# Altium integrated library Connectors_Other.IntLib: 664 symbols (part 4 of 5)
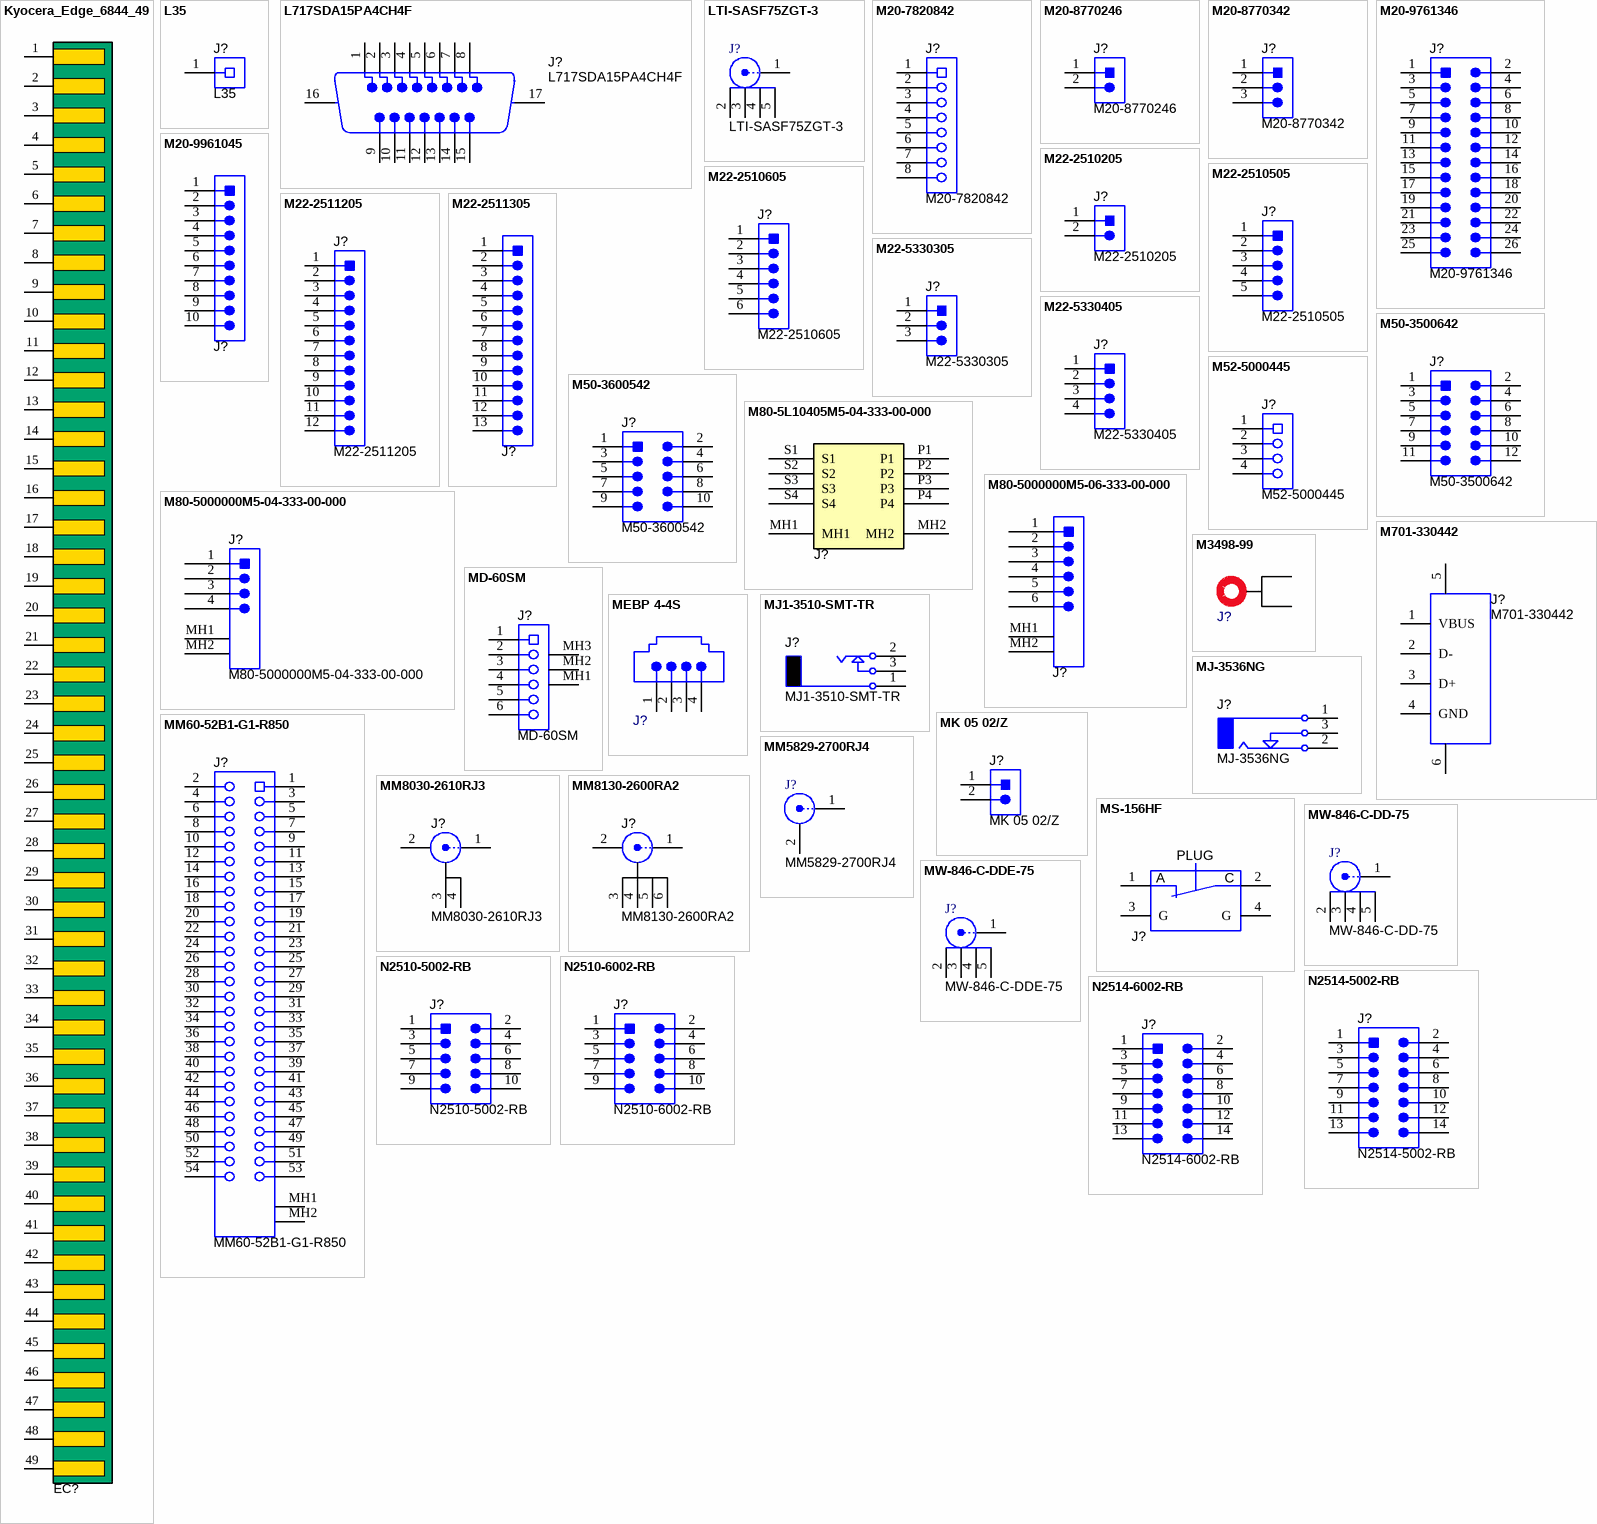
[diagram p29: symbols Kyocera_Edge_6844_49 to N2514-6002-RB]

## M80-5000000M5-04-333-00-000
designator J?
Connector, 4mm, 4x1, Gold, Black, R/A, TH; Manufacturer: Harwin; SymbolCreator: Altium; Pitch_mm: 4; Gender: Male; Shrouded: Y; Row_Count: 1; Current_A: 20
footprint Harwin_M80-5000000M5-04-333-00-000
pins: 1, 2, 3, 4, MH1, MH2

## M80-5000000M5-06-333-00-000
designator J?  (value not drawn)
Connector, 4mm, 6x1, Gold, Black, R/A, TH; Manufacturer: Harwin; SymbolCreator: Altium; Pitch_mm: 4; Gender: Male; Shrouded: Y; Row_Count: 1; Current_A: 20
footprint Harwin_M80-5000000M5-06-333-00-000
pins: 1, 2, 3, 4, 5, 6, MH1, MH2

## M701-330442
designator J?
USB Type B, Gold, White, TH; Manufacturer: Harwin; SymbolCreator: a0412235; Pitch_mm: 2.5; Gender: Female; Shrouded: Y; Row_Count: 2; RowSpacing_mm: 3.2; Current_A: 1.5; Voltage_V: 30
footprint Harwin_M701-330442
pins: 1 VBUS "+5V", 2 D- "Data -", 3 D+ "Data +", 4 GND "Ground", 5 Shield, 6 Shield

## M3498-99
designator J?  (value not drawn)
PC Tail Test Jack, TH; Manufacturer: Harwin; SymbolCreator: Altiumn; Pitch_mm: 10.16; Gender: Female; Row_Count: 1; ContactFinish: Gold; Current_A: 5; Voltage_V: 1500; Cert_UL: Y
footprint Harwin_M3498-99
pins: 1, 2

## MD-60SM
designator J?
Connector, Mini DIN, 3Pos, R/A, TH; Manufacturer: CUI Inc.; SymbolCreator: x0208325; Green_Lifecycle: Not Set; Green_REACh: Incomplete
footprint CUI_MD-60SM
pins: 1, 2, 3, 4, 5, 6, MH1, MH2, MH3

## MEBP 4-4S
designator J?  (value not drawn)
Modular Jack, RJ10, 4P4C, R/A, Gold, TH; Manufacturer: Reichelt; SymbolCreator: Altium; CompType: Connector; Pitch_mm: 1.27; Gender: Female; Row_Count: 2; RowSpacing_mm: 2.54; Cert_UL: Y
footprint Reichelt_MEBP_4-4S
pins: 1, 2, 3, 4

## MJ1-3510-SMT-TR
designator J?
Audio Jack, 3.5mm, Mono, R/A, Black, SMT; Manufacturer: CUI Inc.; SymbolCreator: Altium; CompType: Audio Connector; Gender: Female; ContactFinish: Gold; Current_A: 0.3; Voltage_V: 16
footprint CUI_MJ1-3510
pins: 1 SLEEVE, 2 TIP, 3 TIP SWITCH

## MJ-3536NG
designator J?
Audio Jack, 3.5mm, R/A, Black, TH; Manufacturer: CUI Inc.; SymbolCreator: Altium; CompType: Audio Connector
footprint CUI_MJ-3536NG
pins: 1 SLEEVE, 2 TIP, 3 TIP SWITCH

## MK 05 02/Z
designator J?
Header, 2.54 mm, 2x1, TH; Manufacturer: Fischer Elektronik; SymbolCreator: a0412235
footprint Fischer_MK_05_02
pins: 1, 2
1 alternate drawing of the same symbol

## MM60-52B1-G1-R850
designator J?
Receptacle, 2mm, 27x2, SMD; Manufacturer: JAE Electronics; SymbolCreator: x0208325
footprint JAE_MM60-52B1-G1-R850
pins: 1, 2, 3, 4, 5, 6, 7, 8, 9, 10, 11, 12, 13, 14, 15, 16, 17, 18, 19, 20, 21, 22, 23, 24, 25, 26, 27, 28, 29, 30, 31, 32, 33, 34, 35, 36, 37, 38, 39, 40, 41, 42, 43, 44, 45, 46, 47, 48, 49, 50, 51, 52, 53, 54, MH1, MH2

## MM5829-2700RJ4
designator J?
Connector, RF, 50 Ohm, SMT; Manufacturer: MuRata; SymbolCreator: a0799628; Gender: Male; Shrouded: Y; ContactFinish: Gold
footprint MuRata_MM5829-2700
pins: 1, 2

## MM8030-2610RJ3
designator J?
Coaxial Connectors with Switch, 50 Ohm, SMD; Manufacturer: MuRata; SymbolCreator: Altium; Green_Lifecycle: Not Set; Green_REACh: Incomplete
footprint MuRata_MM8030-2610
pins: 1 IN, 2 OUT, 3 GND (power), 4 GND

## MM8130-2600RA2
designator J?
Coaxial Connectors with Switch, 50 Ohm, SMD; Manufacturer: MuRata; SymbolCreator: a0411947; Gender: Male; Row_Count: 1; ContactFinish: Tin
footprint MuRata_MM8130-2600
pins: 1 IN, 2 OUT, 3 GND, 4 GND (power), 5 GND, 6 GND (power)

## MS-156HF
designator J?  (value not drawn)
CONN COAX JACK STR 50 OHM, SMD; Manufacturer: Hirose Electric Co. Ltd.; SymbolCreator: Altium; CompType: Receptacle; Gender: Female; ContactFinish: Gold; Current_A: 0.1; Voltage_V: 100; Cert_UL: Y
footprint Hirose_MS-156HF
pins: 1 A "NC", 2 C "COM", 3 G, 4 G

## MW-846-C-DD-75
designator J?
F Female Edge Mount, SMT; Manufacturer: Millimeter Wave Technologies; SymbolCreator: X0208326
footprint MWT_MW-846-C-DD-75
pins: 1, 2, 3, 4, 5

## MW-846-C-DDE-75
designator J?
F Female Edge Mount, SMT; Manufacturer: Millimeter Wave Technologies; SymbolCreator: X0208326; Green_Lifecycle: Not Set; Green_REACh: Incomplete
footprint MWT_MW-846-C-DDE-75
pins: 1, 2, 3, 4, 5

## N2510-5002-RB
designator J?
Header (Shrouded), 2.54mm, 5x2, R/A, Gold, Black, TH; Manufacturer: 3M; SymbolCreator: a0412235; Pitch_mm: 2.54; Gender: Male; Shrouded: Y; Row_Count: 2; Current_A: 1.75; Voltage_V: 500
footprint 3M_N2510-50xx
pins: 1, 2, 3, 4, 5, 6, 7, 8, 9, 10

## N2510-6002-RB
designator J?
Header (shrouded), 100mil, 5x2, High-Temperature, Gold, TH; Manufacturer: 3M; SymbolCreator: a0412235; Green_Lifecycle: Active; Green_REACh: Passed
footprint CONN_2510-6002
pins: 1, 2, 3, 4, 5, 6, 7, 8, 9, 10

## N2514-5002-RB
designator J?
Header (shrouded), 100mil, 7x2,  Gold, R/A, TH; Manufacturer: 3M; SymbolCreator: a0412235
footprint CONN_3M_N2514-5002-RB
pins: 1, 2, 3, 4, 5, 6, 7, 8, 9, 10, 11, 12, 13, 14

## N2514-6002-RB
designator J?
Header (shrouded), 100mil, 7x2, Gold, TH; Manufacturer: 3M; SymbolCreator: a0412235; Green_Lifecycle: Active; Green_REACh: Passed
footprint 3M_x2514-60xx
pins: 1, 2, 3, 4, 5, 6, 7, 8, 9, 10, 11, 12, 13, 14

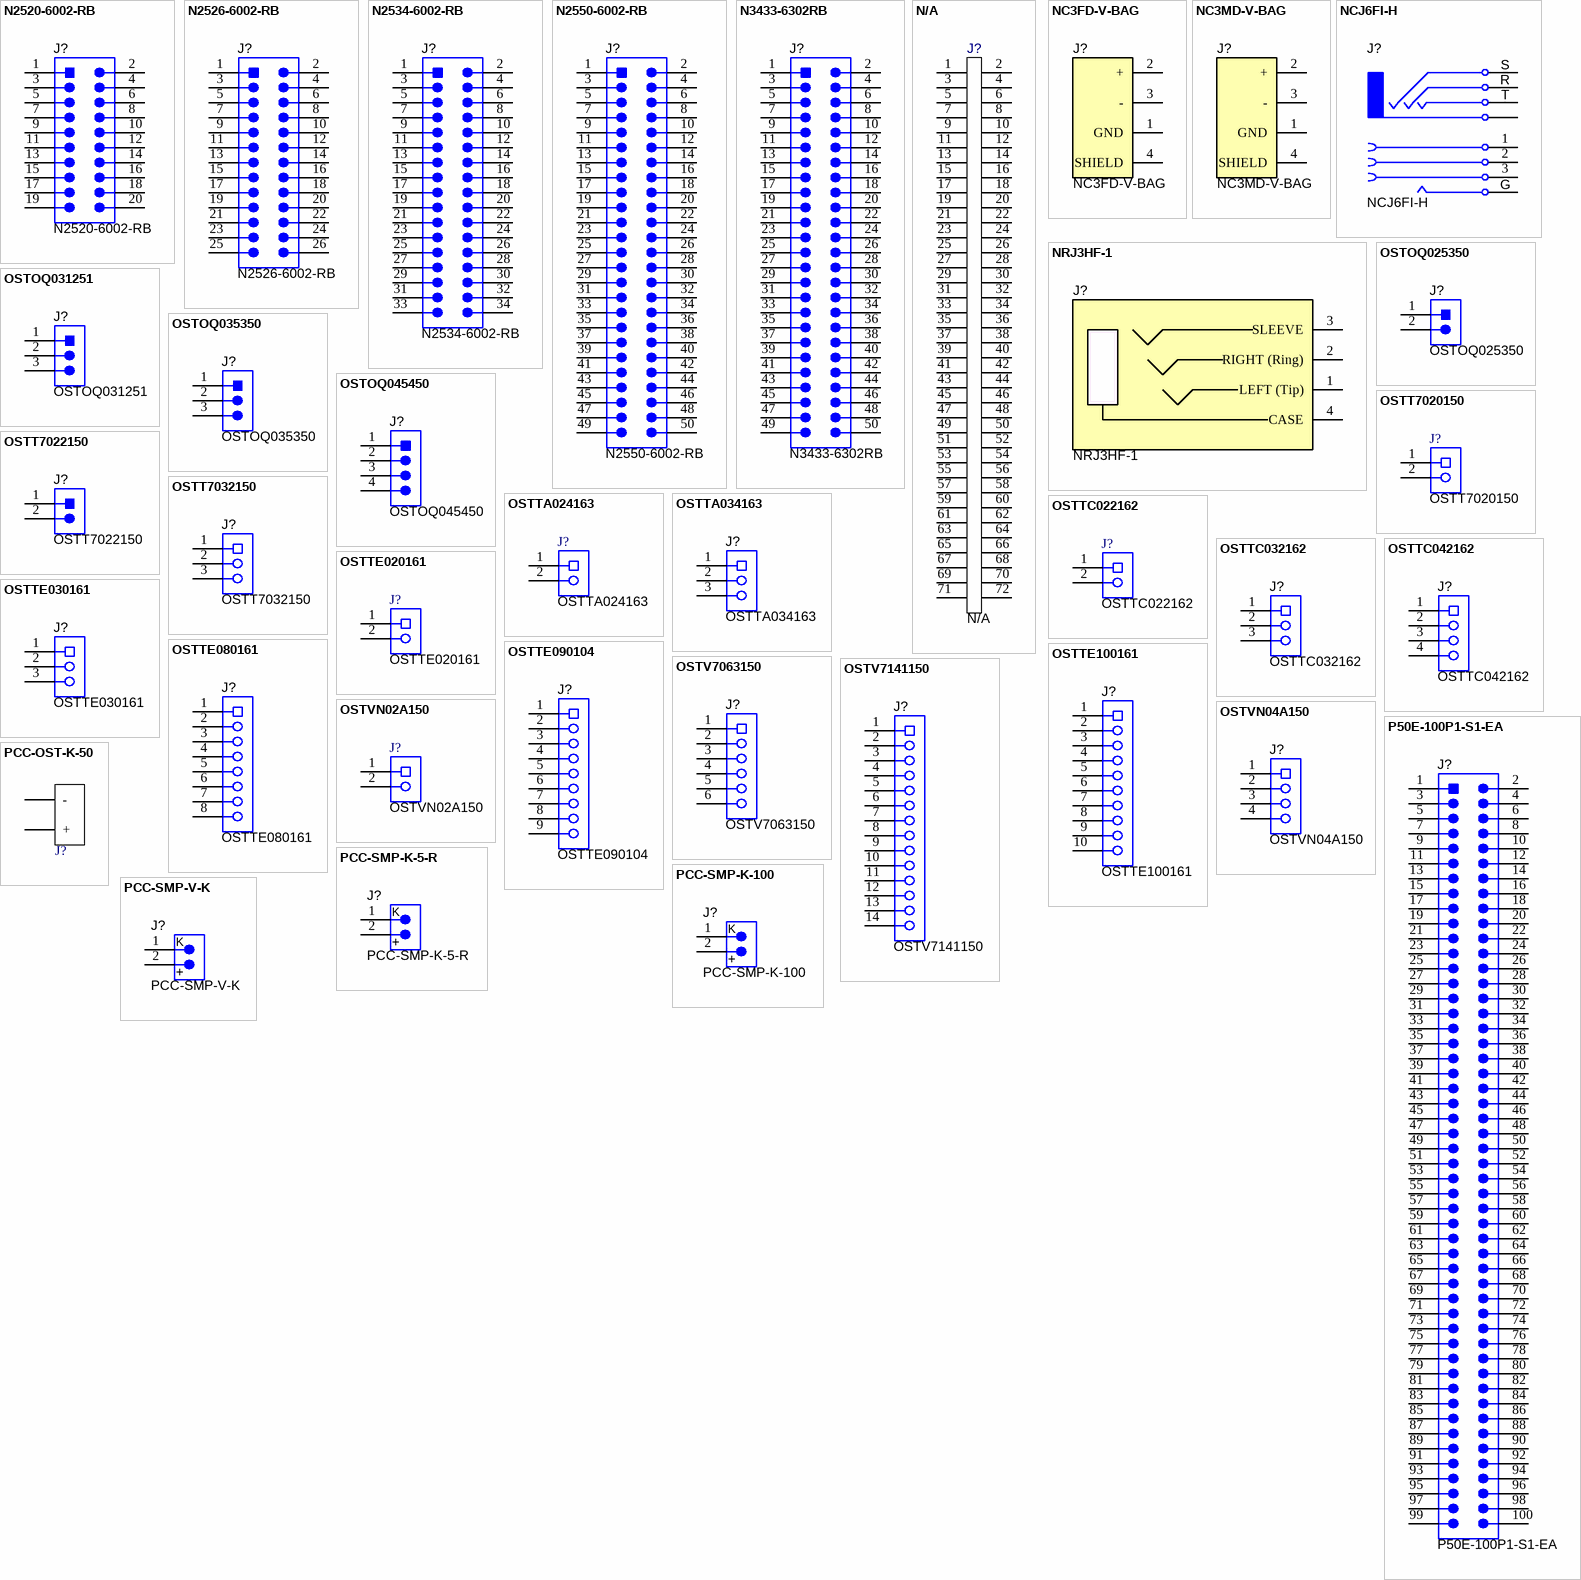
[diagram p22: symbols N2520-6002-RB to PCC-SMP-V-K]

## N2520-6002-RB
designator J?
Header (Shrouded), 2.54mm, 10x2, Gold, Black, TH; Manufacturer: 3M; SymbolCreator: a0412235; Pitch_mm: 2.54; Gender: Male; Shrouded: Y; Row_Count: 2; Green_Lifecycle: Active; Green_REACh: Passed
footprint 3M_N2520-6002
pins: 1, 2, 3, 4, 5, 6, 7, 8, 9, 10, 11, 12, 13, 14, 15, 16, 17, 18, 19, 20

## N2526-6002-RB
designator J?
Header (shrouded), 100mil, 13x2, Gold, TH; Manufacturer: 3M; SymbolCreator: a0412235; Green_Lifecycle: Active; Green_REACh: Passed
footprint CONN_2526-6002
pins: 1, 2, 3, 4, 5, 6, 7, 8, 9, 10, 11, 12, 13, 14, 15, 16, 17, 18, 19, 20, 21, 22, 23, 24, 25, 26

## N2534-6002-RB
designator J?
Header (shrouded), 2.54 mm, 17x2, Gold, TH; Manufacturer: 3M; SymbolCreator: a0411947; Green_Lifecycle: Active; Green_REACh: Passed
footprint 3M_N2534-6002
pins: 1, 2, 3, 4, 5, 6, 7, 8, 9, 10, 11, 12, 13, 14, 15, 16, 17, 18, 19, 20, 21, 22, 23, 24, 25, 26, 27, 28, 29, 30, 31, 32, 33, 34

## N2550-6002-RB
designator J?
Header(Shrouded), 2.54mm, 25x2, Gold, TH; Manufacturer: 3M; SymbolCreator: a0799628; Pitch_mm: 2.54; Gender: Male; Shrouded: Y; Row_Count: 2; Green_Lifecycle: Active; Green_REACh: Passed
footprint 3M_N2550-6002-RB
pins: 1, 2, 3, 4, 5, 6, 7, 8, 9, 10, 11, 12, 13, 14, 15, 16, 17, 18, 19, 20, 21, 22, 23, 24, 25, 26, 27, 28, 29, 30, 31, 32, 33, 34, 35, 36, 37, 38, 39, 40, 41, 42, 43, 44, 45, 46, 47, 48, 49, 50

## N3433-6302RB
designator J?
Header (shrouded), 100mil, 25x2, Gold, TH; Manufacturer: 3M; SymbolCreator: a0799628
footprint 3M_N3433-6302RB
pins: 1, 2, 3, 4, 5, 6, 7, 8, 9, 10, 11, 12, 13, 14, 15, 16, 17, 18, 19, 20, 21, 22, 23, 24, 25, 26, 27, 28, 29, 30, 31, 32, 33, 34, 35, 36, 37, 38, 39, 40, 41, 42, 43, 44, 45, 46, 47, 48, 49, 50

## N/A
designator J?  (no BOM)
Edge Connector; SymbolCreator: a0412235; CompType: Card Edge Footprint
footprint Edge_Connector_36x2
pins: 1, 2, 3, 4, 5, 6, 7, 8, 9, 10, 11, 12, 13, 14, 15, 16, 17, 18, 19, 20, 21, 22, 23, 24, 25, 26, 27, 28, 29, 30, 31, 32, 33, 34, 35, 36, 37, 38, 39, 40, 41, 42, 43, 44, 45, 46, 47, 48, 49, 50, 51, 52, 53, 54, 55, 56, 57, 58, 59, 60, 61, 62, 63, 64, 65, 66, 67, 68, 69, 70, 71, 72

## NC3FD-V-BAG
designator J?
Receptacle, 3 Poles, Vertical, TH; Manufacturer: Neutrik; SymbolCreator: Altium
footprint Neutrik_NC3FD-V
pins: 1 GND, 2 +, 3 -, 4 SHIELD

## NC3MD-V-BAG
designator J?
Connector, 3 pole male receptacle, TH; Manufacturer: Neutrik; SymbolCreator: Altium; Shrouded: Y
footprint Neutrik_NC3MD-V-BAG
pins: 1 GND, 2 +, 3 -, 4 SHIELD

## NCJ6FI-H
designator J?
XLR Receptacle and 1/4" Phone Jack, 8-Pin, TH; Manufacturer: Neutrik; SymbolCreater: Altium; CompType: Audio Connector; Green_Lifecycle: Not Set; Green_REACh: Incomplete
footprint Neutrik_NCJ6FI-H
pins: 1 "Tip/Left Channel/(+)", 2, 3, 4 G (power) "Sleeve (Ground)", 5 S, 6 R, 7 T, 8

## NRJ3HF-1
designator J?
Phone Jack, 1/4", TH; Manufacturer: Neutrik; SymbolCreator: Altium; CompType: Audio Connector; Green_Lifecycle: Not Set; Green_REACh: Incomplete
footprint Neutrik_NRJ3HF-1
pins: 1 LEFT (Tip), 2 RIGHT (Ring), 3 SLEEVE, 4 CASE

## OSTOQ025350
designator J?
Header(shrouded), 5.08mm, 2x1, Tin, TH; Manufacturer: On-Shore Technology; SymbolCreator: a0412235; Pitch_mm: 5.08; Gender: Male; Shrouded: Y; Row_Count: 1; Current_A: 20; Voltage_V: 300
footprint On-Shore_OSTOQ025350
pins: 1, 2
1 alternate drawing of the same symbol

## OSTOQ031251
designator J?
Terminal Block, 3.5mm, 3x1, TH; Manufacturer: On-Shore Technology; SymbolCreator: a0799628; Note: Mating Part number: OSTTJ0311530
footprint On-Shore_OSTOQ031251
pins: 1, 2, 3
3 alternate drawings of the same symbol

## OSTOQ035350
designator J?
Header(shrouded), 5.08mm, 3x1, Tin, TH; Manufacturer: On-Shore Technology; SymbolCreator: a0799628; Pitch_mm: 5.08; Gender: Male; Shrouded: Y; Row_Count: 1; Current_A: 20; Voltage_V: 300
footprint On-Shore_OSTOQ035350
pins: 1, 2, 3
3 alternate drawings of the same symbol

## OSTOQ045450
designator J?
Header(shrouded), 5.08mm, 4x1, Tin, Green, TH; Manufacturer: On-Shore Technology; SymbolCreator: a0412235; Pitch_mm: 5.08; Gender: Male; Shrouded: Y; Row_Count: 1; Current_A: 20; Voltage_V: 300
footprint On-Shore_OSTOQ045450
pins: 1, 2, 3, 4

## OSTT7020150
designator J?
Terminal Block, 6.35mm, 2x1, TH; Manufacturer: On-Shore Technology; SymbolCreator: a0412235; Pitch_mm: 6.35; Gender: Female; Row_Count: 1; Current_A: 30; Voltage_V: 300; Cert_UL: Y
footprint On-Shore_OSTT7020150
pins: 1, 2

## OSTT7022150
designator J?
Terminal Block, 30A, 9.52mm (.375) Pitch, 2-Pos, TH; Manufacturer: On-Shore Technology; SymbolCreator: a0412235; Green_Lifecycle: Not Set; Green_REACh: Incomplete
footprint TERM_BLK_OSTT7022150
pins: 1, 2
1 alternate drawing of the same symbol

## OSTT7032150
designator J?
Terminal Block, 3x1, 9.52mm, TH; Manufacturer: On-Shore Technology; SymbolCreator: a0412235; Pitch_mm: 9.52; Gender: Female; Row_Count: 1; ContactFinish: Brass; Green_Lifecycle: Not Set; Green_REACh: Incomplete
footprint On-Shore_OSTT7032150
pins: 1, 2, 3

## OSTTA024163
designator J?
Terminal Block, 2x1, 5.08mm, TH; Manufacturer: On-Shore Technology; SymbolCreator: a0412235; Green_Lifecycle: Not Set; Green_REACh: Incomplete
footprint On-Shore_OSTTA024163
pins: 1, 2

## OSTTA034163
designator J?
Terminal Block, 3x1, 5.08 mm, TH; Manufacturer: On-Shore Technology; SymbolCreator: a0412235; Green_Lifecycle: Not Set; Green_REACh: Incomplete
footprint On-Shore_OSTTA034163
pins: 1, 2, 3

## OSTTC022162
designator J?
Terminal Block, 2-pole, 200mil, TH; Manufacturer: On-Shore Technology; SymbolCreator: a0412235; Green_Lifecycle: Not Set; Green_REACh: Incomplete
footprint On-Shore_OSTTC022162
pins: 1, 2

## OSTTC032162
designator J?
Terminal Block, 3x1, 5.08 mm, Tin, TH; Manufacturer: On-Shore Technology; SymbolCreator: a0412235; Pitch_mm: 5.08; Gender: Female; Row_Count: 1; Current_A: 15; Voltage_V: 300; Cert_UL: Y
footprint On-Shore_OSTTC032162
pins: 1, 2, 3

## OSTTC042162
designator J?
Terminal Block, 5.08 mm, 4x1, Tin, Blue, TH; Manufacturer: On-Shore Technology; SymbolCreator: a0411947
footprint On-Shore_OSTTC042162
pins: 1, 2, 3, 4

## OSTTE020161
designator J?
Terminal Block, 2x1, 3.5mm, TH; Manufacturer: On-Shore Technology; SymbolCreator: a0412235; Green_Lifecycle: Not Set; Green_REACh: Incomplete
footprint On-Shore_OSTTE020161
pins: 1, 2

## OSTTE030161
designator J?
Terminal Block, 3.5mm, 3x1, Tin, R/A, TH; Manufacturer: On-Shore Technology; SymbolCreator: a0412235; Pitch_mm: 3.5; Gender: Female; Row_Count: 1; Current_A: 10; Voltage_V: 125; Cert_CSA: Y; Green_Lifecycle: Not Set; Green_REACh: Incomplete
footprint On-Shore_OSTTE030161
pins: 1, 2, 3

## OSTTE080161
designator J?
Terminal Block, 8x1, 3.5mm, TH; Manufacturer: On-Shore Technology; SymbolCreator: a0411947; Green_Lifecycle: Not Set; Green_REACh: Incomplete
footprint On-Shore_OSTTE080161
pins: 1, 2, 3, 4, 5, 6, 7, 8

## OSTTE090104
designator J?
Terminal Block, 3.5mm, 9x1, TH; Manufacturer: On-Shore Technology; SymbolCreator: x0208325; Pitch_mm: 3.5; Gender: Female; Row_Count: 1; ContactFinish: Tin; Current_A: 10; Voltage_V: 125; Cert_UL: Y
footprint On-Shore_OSTTE090104
pins: 1, 2, 3, 4, 5, 6, 7, 8, 9

## OSTTE100161
designator J?
Terminal Block, 3.5mm, 10x1, Tin, Blue, TH; Manufacturer: On-Shore Technology; SymbolCreator: a0411947; Pitch_mm: 3.5; Gender: Female; Row_Count: 1; Current_A: 10; Voltage_V: 125; Cert_CSA: Y; Green_Lifecycle: Not Set; Green_REACh: Incomplete
footprint On-Shore_OSTTE100161
pins: 1, 2, 3, 4, 5, 6, 7, 8, 9, 10

## OSTV7063150
designator J?
Terminal Block, 3.81mm, 6x1, Tin, TH; Manufacturer: On-Shore Technology; SymbolCreator: a0411947; Pitch_mm: 3.81; Gender: Female; Row_Count: 1; Current_A: 8; Voltage_V: 300; Cert_UL: Y
footprint On-Shore_OSTV7063150
pins: 1, 2, 3, 4, 5, 6

## OSTV7141150
designator J?
Terminal Block, 3.5mm, 14x1, Tin, TH; Manufacturer: On-Shore Technology; SymbolCreator: a0411947; Pitch_mm: 3.5; Gender: Female; Row_Count: 1; Current_A: 8; Voltage_V: 300; Cert_UL: Y
footprint On-Shore_OSTV7141150
pins: 1, 2, 3, 4, 5, 6, 7, 8, 9, 10, 11, 12, 13, 14

## OSTVN02A150
designator J?
Terminal Block, 2.54mm, 2x1, Brass, TH; Manufacturer: On-Shore Technology; SymbolCreator: a0412235; Green_Lifecycle: Not Set; Green_REACh: Incomplete
footprint On-Shore_OSTVN02A150
pins: 1, 2

## OSTVN04A150
designator J?
Terminal Block, 2.54mm, 4x1, Brass, TH; Manufacturer: On-Shore Technology; SymbolCreator: a0411947
footprint On-Shore_OSTVN04A150
pins: 1, 2, 3, 4

## P50E-100P1-S1-EA
designator J?
Header, 1.27mm, 50x2, Gold, TH; Manufacturer: 3M; SymbolCreator: a0799628; Pitch_mm: 1.25; Gender: Male; Row_Count: 2
footprint 3M_P50E-100P1-S1-xx
pins: 1, 2, 3, 4, 5, 6, 7, 8, 9, 10, 11, 12, 13, 14, 15, 16, 17, 18, 19, 20, 21, 22, 23, 24, 25, 26, 27, 28, 29, 30, 31, 32, 33, 34, 35, 36, 37, 38, 39, 40, 41, 42, 43, 44, 45, 46, 47, 48, 49, 50, 51, 52, 53, 54, 55, 56, 57, 58, 59, 60, 61, 62, 63, 64, 65, 66, 67, 68, 69, 70, 71, 72, 73, 74, 75, 76, 77, 78, 79, 80, 81, 82, 83, 84, 85, 86, 87, 88, 89, 90, 91, 92, 93, 94, 95, 96, 97, 98, 99, 100

## PCC-OST-K-50
designator J?  (value not drawn)
Connector, TH, Thermocouple type K; Manufacturer: Omega; Value: Type K; U/M: EA
footprint PCC-OST
pins: 1 -, 2 +

## PCC-SMP-K-5-R
designator J?
Circuit Board Thermocouple Connector, Miniature Size, Type K, Horizontal installation, TH; Manufacturer: Omega; SymbolCreator: a0799628
footprint Omega_PCC-SMP-K
pins: 1, 2
1 alternate drawing of the same symbol

## PCC-SMP-K-100
designator J?
Thermocouple Connectors, Type PCC, TH; Manufacturer: Omega; SymbolCreator: a0799628
footprint Omega_PCC-SMP-K
pins: 1, 2
1 alternate drawing of the same symbol

## PCC-SMP-V-K
designator J?
Thermocouple Connectors, Type PCC, TH; Manufacturer: Omega; SymbolCreator: a0799628
footprint Omega_PCC-SMP-V-K
pins: 1, 2
1 alternate drawing of the same symbol

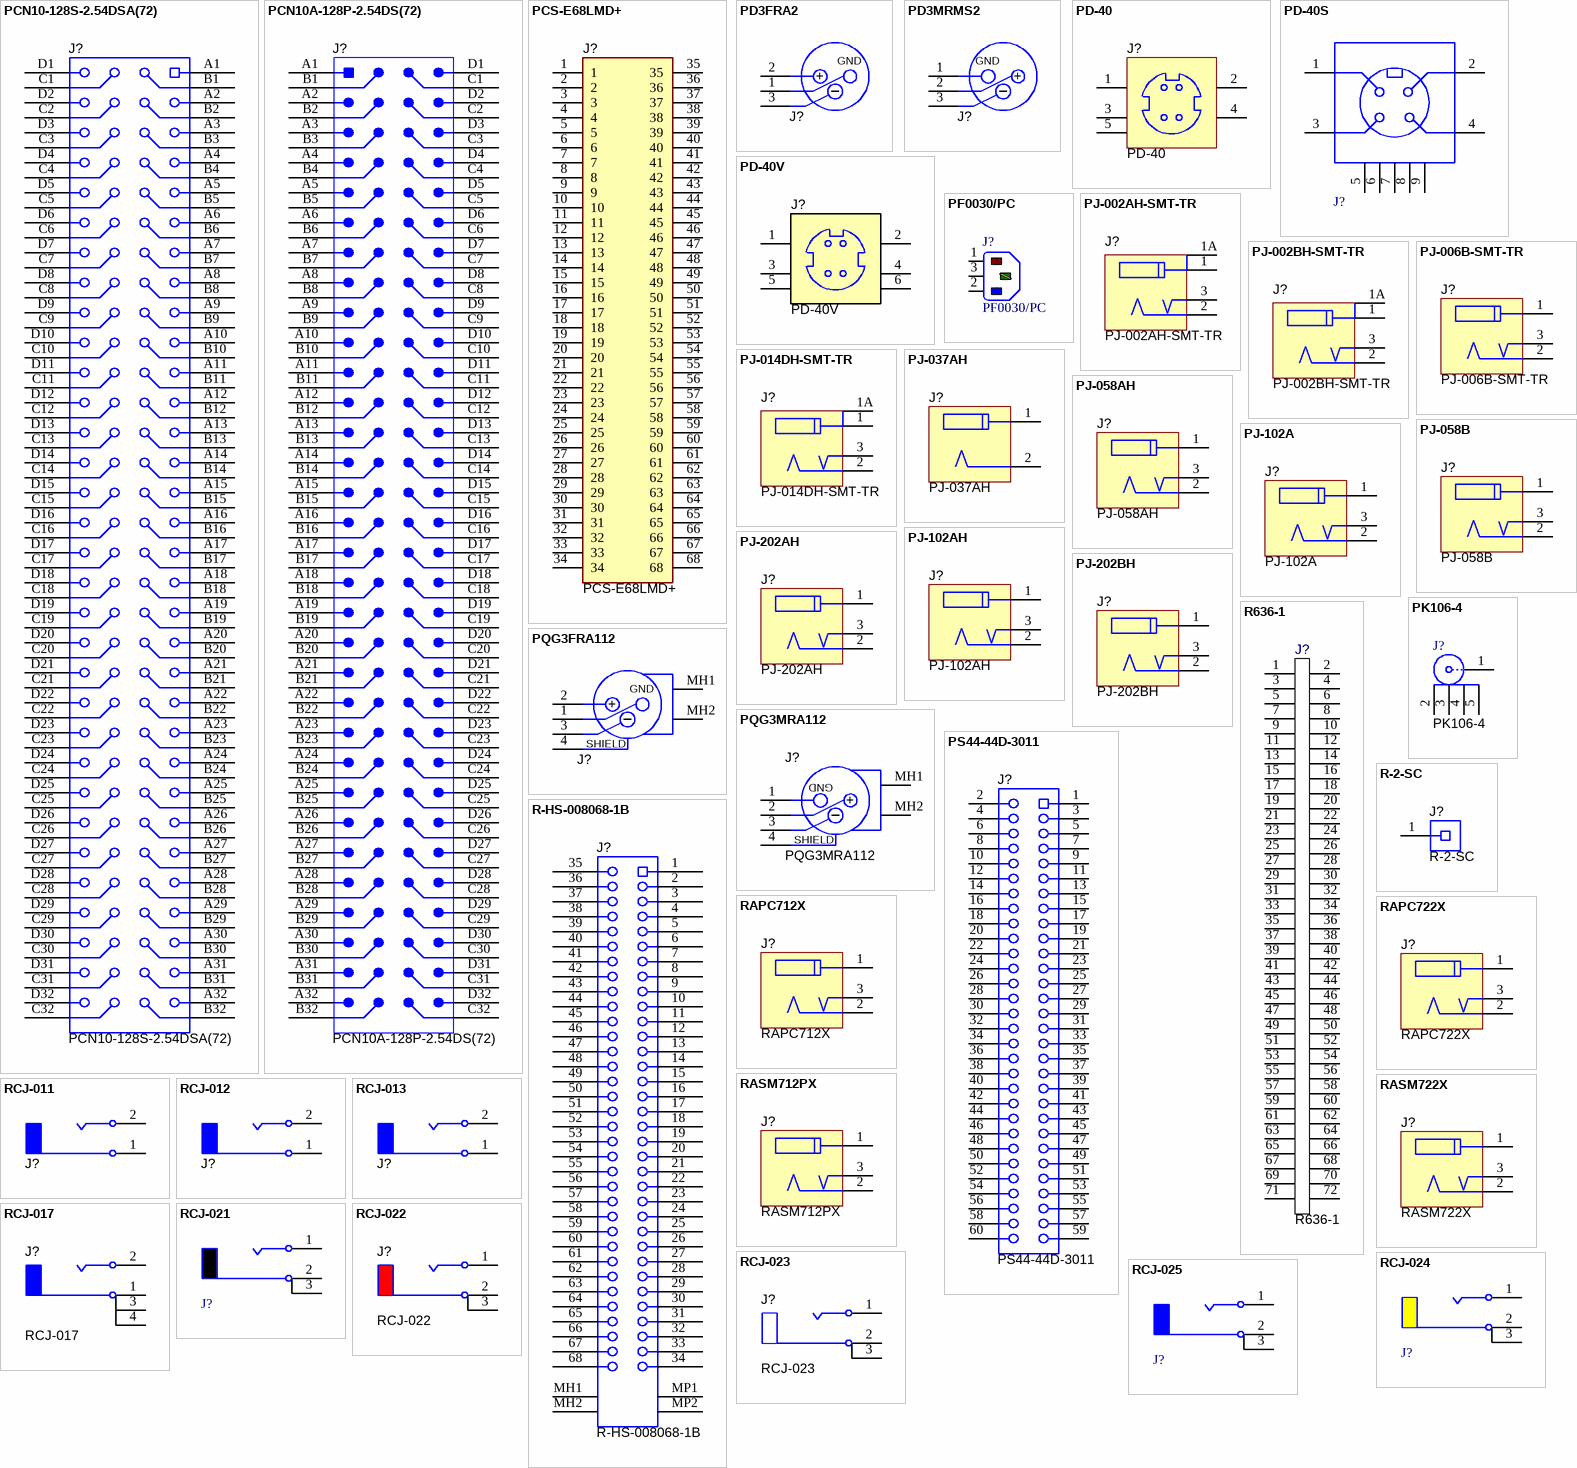
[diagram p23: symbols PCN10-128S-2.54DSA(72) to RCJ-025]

## PCN10-128S-2.54DSA(72)
designator J?
Receptacle, 2.54mm, 32x4, Gold, TH; Manufacturer: Hirose Electric Co. Ltd.; SymbolCreator: Altium; Pitch_mm: 2.54; Gender: Female; Row_Count: 4
footprint Hirose_PCN10-128S-2_54DSA_72
pins: A1, A2, A3, A4, A5, A6, A7, A8, A9, A10, A11, A12, A13, A14, A15, A16, A17, A18, A19, A20, A21, A22, A23, A24, A25, A26, A27, A28, A29, A30, A31, A32, B1, B2, B3, B4, B5, B6, B7, B8, B9, B10, B11, B12, B13, B14, B15, B16, B17, B18, B19, B20, B21, B22, B23, B24, B25, B26, B27, B28, B29, B30, B31, B32, C1, C2, C3, C4, C5, C6, C7, C8, C9, C10, C11, C12, C13, C14, C15, C16, C17, C18, C19, C20, C21, C22, C23, C24, C25, C26, C27, C28, C29, C30, C31, C32, D1, D2, D3, D4, D5, D6, D7, D8, D9, D10, D11, D12, D13, D14, D15, D16, D17, D18, D19, D20, D21, D22, D23, D24, D25, D26, D27, D28, D29, D30, D31, D32

## PCN10A-128P-2.54DS(72)
designator J?
Header, 2.54mm, 32x4, Gold, R/A, TH; Manufacturer: Hirose Electric Co. Ltd.; SymbolCreator: Altium; Pitch_mm: 2.54; Gender: Male; Row_Count: 4
footprint Hirose_PCN10A-128P-2_54DS_72
pins: A1, A2, A3, A4, A5, A6, A7, A8, A9, A10, A11, A12, A13, A14, A15, A16, A17, A18, A19, A20, A21, A22, A23, A24, A25, A26, A27, A28, A29, A30, A31, A32, B1, B2, B3, B4, B5, B6, B7, B8, B9, B10, B11, B12, B13, B14, B15, B16, B17, B18, B19, B20, B21, B22, B23, B24, B25, B26, B27, B28, B29, B30, B31, B32, C1, C2, C3, C4, C5, C6, C7, C8, C9, C10, C11, C12, C13, C14, C15, C16, C17, C18, C19, C20, C21, C22, C23, C24, C25, C26, C27, C28, C29, C30, C31, C32, D1, D2, D3, D4, D5, D6, D7, D8, D9, D10, D11, D12, D13, D14, D15, D16, D17, D18, D19, D20, D21, D22, D23, D24, D25, D26, D27, D28, D29, D30, D31, D32

## PCS-E68LMD+
designator J?
Connector, SCSI, M, 68-Pos, 1.27mm Pitch, R/A, TH; Manufacturer: Honda Tsushin Kogyo; SymbolCreator: a0799721
footprint CONN_PCS-E68LMD+
pins: 1, 2, 3, 4, 5, 6, 7, 8, 9, 10, 11, 12, 13, 14, 15, 16, 17, 18, 19, 20, 21, 22, 23, 24, 25, 26, 27, 28, 29, 30, 31, 32, 33, 34, 35, 36, 37, 38, 39, 40, 41, 42, 43, 44, 45, 46, 47, 48, 49, 50, 51, 52, 53, 54, 55, 56, 57, 58, 59, 60, 61, 62, 63, 64, 65, 66, 67, 68

## PD3FRA2
designator J?  (value not drawn)
Receptacle, 3 Contacts, Tin, R/A, TH; Manufacturer: Switchcraft; SymbolCreator: Altium; Pitch_mm: 4; Gender: Female
footprint Switchcraft_PD3FRA2
pins: 1 GND, 2 +, 3 -

## PD3MRMS2
designator J?  (value not drawn)
Connector, Male Pin, 3 Contacts, Silver, R/A, TH; Manufacturer: Switchcraft; SymbolCreator: Altium; Pitch_mm: 4; Shrouded: Y
footprint Switchcraft_PD3MRMS2
pins: 1 GND, 2 +, 3 -

## PD-40
designator J?
Power Jack, Tin, R/A, TH; Manufacturer: CUI Inc.; SymbolCreator: Altium
footprint CUI_PD-40
pins: 1, 2, 3, 4, 5

## PD-40S
designator J?  (value not drawn)
Power DIN Jack, 4 Pos, R/A, Tin, TH; Manufacturer: CUI Inc.; SymbolCreator: Altium; Gender: Female; Current_A: 7.5; Voltage_V: 20
footprint CUI_PD-40S
pins: 1, 2, 3  , 4  , 5  , 6  , 7   (power), 8   (power), 9

## PD-40V
designator J?
Power Jack, Silver, TH; Manufacturer: CUI Inc.; SymbolCreator: Altium; Gender: Female; Shrouded: N
footprint CUI_PD-40V
pins: 1, 2, 3, 4, 5, 6

## PF0030/PC
designator J?
IEC Connector, PC Flange Mount Fused Inlet, 10A, 250V, TH; Manufacturer: Bulgin; SymbolCreator: Altium; CompType: Socket
footprint Bulgin_PF0030_PC
pins: 1 L (power) "Live (Active)", 2 N (power) "Neutral", 3 E (power) "Earth (Ground)"

## PJ-002AH-SMT-TR
designator J?
Power Jack, SMT; Manufacturer: CUI Inc.; SymbolCreator: a0411947; Green_Lifecycle: Not Set; Green_REACh: Incomplete
footprint CUI_PJ-002AH-SMT
pins: 1, 1A, 2, 3

## PJ-002BH-SMT-TR
designator J?
Power Jack, 2.5x5.5mm, R/A, SMT; Manufacturer: CUI Inc.; SymbolCreator: a0411947; Pitch_mm: 6.1; Gender: Female; Row_Count: 2; RowSpacing_mm: 11.4; ContactFinish: Silver; Current_A: 5; Voltage_V: 24; Cert_UL: Y
footprint CUI_PJ-002BH-SMT-TR
pins: 1, 1A, 2, 3

## PJ-006B-SMT-TR
designator J?
DC Power Jack, SMT; Manufacturer: CUI Inc.; SymbolCreator: a0799628; Gender: Male; Current_A: 4; Voltage_V: 18; Cert_UL: Y
footprint CUI_PJ-006B-SMT-TR
pins: 1, 2, 3

## PJ-014DH-SMT-TR
designator J?
Power Jack, Nickel, R/A, SMD; Manufacturer: CUI Inc.; SymbolCreator: a0411947
footprint CUI_PJ-014DH-SMT-TR
pins: 1, 1A, 2, 3

## PJ-037AH
designator J?
Power Jack, 2mm, R/A, TH; Manufacturer: CUI Inc.; SymbolCreator: Altium; Pitch_mm: 6; Gender: Male; Shrouded: N; Row_Count: 1
footprint CUI_PJ-037AH
pins: 1, 2

## PJ-058AH
designator J?
Connector, DC Jack 2.5 mm Center Pin, TH; Manufacturer: CUI Inc.; SymbolCreator: a0799628; CompType: Power Jack; Green_Lifecycle: Not Set; Green_REACh: Incomplete
footprint CUI_PJ-058AH
pins: 1, 2, 3

## PJ-058B
designator J?
Connector, DC Jack 2.5 mm Center Pin, TH; Manufacturer: CUI Inc.; SymbolCreator: a0799628; CompType: Power Jack; Gender: Female; ContactFinish: Nickel; Current_A: 2.5; Voltage_V: 24; Cert_UL: Y
footprint CUI_PJ-058B
pins: 1, 2, 3

## PJ-102A
designator J?
Connector, DC Jack 2.1X5.5 mm, TH; Manufacturer: CUI Inc.; SymbolCreator: a0799628; Green_Lifecycle: Not Set; Green_REACh: Incomplete
footprint CONN_PJ-102A
footprint CUI_PJ-102A_NoSlots
pins: 1, 2, 3

## PJ-102AH
designator J?
DC POWER JACK, R/A, TH; Manufacturer: CUI Inc.; SymbolCreator: a0799628; Gender: Male; Current_A: 5; Voltage_V: 24; Cert_UL: Y; Green_Lifecycle: Not Set; Green_REACh: Incomplete
footprint CUI_PJ-102AH
pins: 1, 2, 3

## PJ-202AH
designator J?
Connector, DC Jack 2.1X5.5 mm, TH; Manufacturer: CUI Inc.; SymbolCreator: a0799628; CompType: Power Jack; Green_Lifecycle: Not Set; Green_REACh: Incomplete
footprint CONN_CUI-PJ-202AH
footprint CONN_CUI-PJ-202AH_NoSlots
pins: 1, 2, 3

## PJ-202BH
designator J?
Connector, DC Jack 2.5 mm Center Pin, TH; Manufacturer: CUI Inc.; SymbolCreator: a0799628; CompType: Power Jack
footprint CUI_PJ-202BH
footprint CUI_PJ-202BH_NoSlots
pins: 1, 2, 3

## PK106-4
designator J?
Probe Tip to PCB Adapter, TH; Manufacturer: Teledyne LeCroy
footprint Lecroy_PK106-4
pins: 1, 2, 3, 4, 5

## PQG3FRA112
designator J?  (value not drawn)
Receptacle, 160mil, 3 Position, R/A, TH; Manufacturer: Switchcraft; SymbolCreator: Altium; Pitch_mm: 4.1; Gender: Female; Shrouded: Y; Row_Count: 1; Green_Lifecycle: Not Set; Green_REACh: Incomplete
footprint Switchcraft_PQG3FRA112
pins: 1 GND, 2 +, 3 -, 4 SHIELD, MH1, MH2

## PQG3MRA112
designator J?
Receptacle, Male, 3 Position, R/A, TH; Manufacturer: Switchcraft; SymbolCreator: Altium; Green_Lifecycle: Not Set; Green_REACh: Incomplete
footprint Switchcraft_PQG3MRA112
pins: 1 GND, 2 +, 3 -, 4 SHIELD, MH1, MH2

## PS44-44D-3011
designator J?
Edge Card Connector, 2.54, 44x2, TH; Manufacturer: Yamaichi Electronics; SymbolCreator: Altium; CompType: Card Edge Socket; Pitch_mm: 2.54; Gender: Female; Row_Count: 2; Current_A: 3; Voltage_V: 100
footprint Yamaichi_PS44-44D-3011
pins: 1, 2, 3, 4, 5, 6, 7, 8, 9, 10, 11, 12, 13, 14, 15, 16, 17, 18, 19, 20, 21, 22, 23, 24, 25, 26, 27, 28, 29, 30, 31, 32, 33, 34, 35, 36, 37, 38, 39, 40, 41, 42, 43, 44, 45, 46, 47, 48, 49, 50, 51, 52, 53, 54, 55, 56, 57, 58, 59, 60
1 alternate drawing of the same symbol

## R636-1
designator J?
Edge Connector; Manufacturer: Vector Electronics; SymbolCreator: a0412235
footprint R636-1
pins: 1, 2, 3, 4, 5, 6, 7, 8, 9, 10, 11, 12, 13, 14, 15, 16, 17, 18, 19, 20, 21, 22, 23, 24, 25, 26, 27, 28, 29, 30, 31, 32, 33, 34, 35, 36, 37, 38, 39, 40, 41, 42, 43, 44, 45, 46, 47, 48, 49, 50, 51, 52, 53, 54, 55, 56, 57, 58, 59, 60, 61, 62, 63, 64, 65, 66, 67, 68, 69, 70, 71, 72

## R-2-SC
designator J?
Pin Receptacle, Gold, TH; Manufacturer: Interconnect Devices; SymbolCreator: a0799628; Gender: Female; Current_A: 3
footprint IDI_R-2-SC
pins: 1

## R-HS-008068-1B
designator J?
Receptacle, 0.8 mm, 34x2, Gold, TH; Manufacturer: All Best Electronics; SymbolCreator: Altium
footprint ALLBEST_R-HS-008068-1B
pins: 1, 2, 3, 4, 5, 6, 7, 8, 9, 10, 11, 12, 13, 14, 15, 16, 17, 18, 19, 20, 21, 22, 23, 24, 25, 26, 27, 28, 29, 30, 31, 32, 33, 34, 35, 36, 37, 38, 39, 40, 41, 42, 43, 44, 45, 46, 47, 48, 49, 50, 51, 52, 53, 54, 55, 56, 57, 58, 59, 60, 61, 62, 63, 64, 65, 66, 67, 68, MH1, MH2, MP1, MP2

## RAPC712X
designator J?
Power Jack, mini, 2.5mm OD, R/A, TH; Manufacturer: Switchcraft; SymbolCreator: a0799628; Green_Lifecycle: Not Set; Green_REACh: Incomplete
footprint CONN_RAPC712X
pins: 1, 2, 3

## RAPC722X
designator J?
Power Jack, mini, 2.1mm OD, R/A, TH; Manufacturer: Switchcraft; SymbolCreator: a0799628; Green_Lifecycle: Not Set; Green_REACh: Incomplete
footprint CONN_RAPC722X
pins: 1, 2, 3

## RASM712PX
designator J?
Power Jack, 2.5mm, R/A, SMT; Manufacturer: Switchcraft; SymbolCreator: a0799628
footprint Switchcraft_RASM712PX
pins: 1, 2, 3

## RASM722X
designator J?
Power Jack, 2mm, R/A, SMD; Manufacturer: Switchcraft; SymbolCreator: a0799628
footprint Switchcraft_RASM722
pins: 1, 2, 3

## RCJ-011
designator J?  (value not drawn)
RCA Jack, 1Pos, Tin, R/A, TH; Manufacturer: CUI Inc.; SymbolCreator: Altium; CompType: Audio Connector; Gender: Female; Row_Count: 1; Voltage_V: 500; Green_Lifecycle: Not Set; Green_REACh: Incomplete
footprint CUI_RCJ-011
pins: 1 SLEEVE "Tip/Left Channel/(+)", 2 TIP (power) "Sleeve (Ground)"

## RCJ-012
designator J?  (value not drawn)
RCA Jack, 1Pos, Tin, Red, R/A, TH; Manufacturer: CUI Inc.; SymbolCreator: Altium; CompType: Audio Connector; Gender: Female; Row_Count: 1; Voltage_V: 500; Green_Lifecycle: Not Set; Green_REACh: Incomplete
footprint CUI_RCJ-012
pins: 1 SLEEVE "Tip/Left Channel/(+)", 2 TIP (power) "Sleeve (Ground)"

## RCJ-013
designator J?  (value not drawn)
RCA Jack, 1Pos, Tin, White, R/A, TH; Manufacturer: CUI Inc.; SymbolCreator: Altium; CompType: Audio Connector; Gender: Female; Row_Count: 1; Voltage_V: 500; Green_Lifecycle: Not Set; Green_REACh: Incomplete
footprint CUI_RCJ-013
pins: 1 SLEEVE "Tip/Left Channel/(+)", 2 TIP (power) "Sleeve (Ground)"

## RCJ-017
designator J?
Connector, Phono 3.2 mm Shaft, 9 mm OD, RA, TH; Manufacturer: CUI Inc.; SymbolCreator: a0799628; CompType: Audio Connector; Green_Lifecycle: Not Set; Green_REACh: Incomplete
footprint CUI_RCJ-01X
pins: 1 SLEEVE "Tip/Left Channel/(+)", 2 TIP (power) "Sleeve (Ground)", 3 SLEEVE "Ring/Right Channel/(-)", 4 SLEEVE "Ring/Right Channel/(-)"

## RCJ-021
designator J?  (value not drawn)
RCA Jack, Vertical, Black, TH; Manufacturer: CUI Inc.; SymbolCreator: Altium; CompType: Audio Connector; Gender: Female; ContactFinish: Tin; Voltage_V: 500; Green_Lifecycle: Not Set; Green_REACh: Incomplete
footprint CONN_RCJ-021
pins: 1 "Tip/Left Channel/(+)", 2 (power) "Sleeve (Ground)", 3 R "Ring/Right Channel/(-)"

## RCJ-022
designator J?
RCA Jack, Vertical, Red, TH; Manufacturer: CUI Inc.; SymbolCreator: a0412235; CompType: Audio Connector; Green_Lifecycle: Not Set; Green_REACh: Incomplete
footprint CONN_RCJ-022
pins: 1 "Tip/Left Channel/(+)", 2 (power) "Sleeve (Ground)", 3 R "Ring/Right Channel/(-)"

## RCJ-023
designator J?
RCA Jack, Vertical, White, TH; Manufacturer: CUI Inc.; SymbolCreator: a0411947; CompType: Audio Connector; Green_Lifecycle: Not Set; Green_REACh: Incomplete
footprint CONN_RCJ-023
pins: 1 "Tip/Left Channel/(+)", 2 (power) "Sleeve (Ground)", 3 R "Ring/Right Channel/(-)"

## RCJ-024
designator J?  (value not drawn)
RCA Jack, Vertical, Yellow, TH; Manufacturer: CUI Inc.; SymbolCreator: Altium; CompType: Audio Connector; Gender: Female; ContactFinish: Tin; Voltage_V: 500
footprint CONN_RCJ-024
pins: 1 "Tip/Left Channel/(+)", 2 (power) "Sleeve (Ground)", 3 R "Ring/Right Channel/(-)"

## RCJ-025
designator J?  (value not drawn)
RCA Jack, Vertical, Blue, TH; Manufacturer: CUI Inc.; SymbolCreator: Altium; CompType: Audio Connector; Gender: Female; ContactFinish: Tin; Voltage_V: 500; Green_Lifecycle: Not Set; Green_REACh: Incomplete
footprint CONN_RCJ-025
pins: 1 "Tip/Left Channel/(+)", 2 (power) "Sleeve (Ground)", 3 R "Ring/Right Channel/(-)"

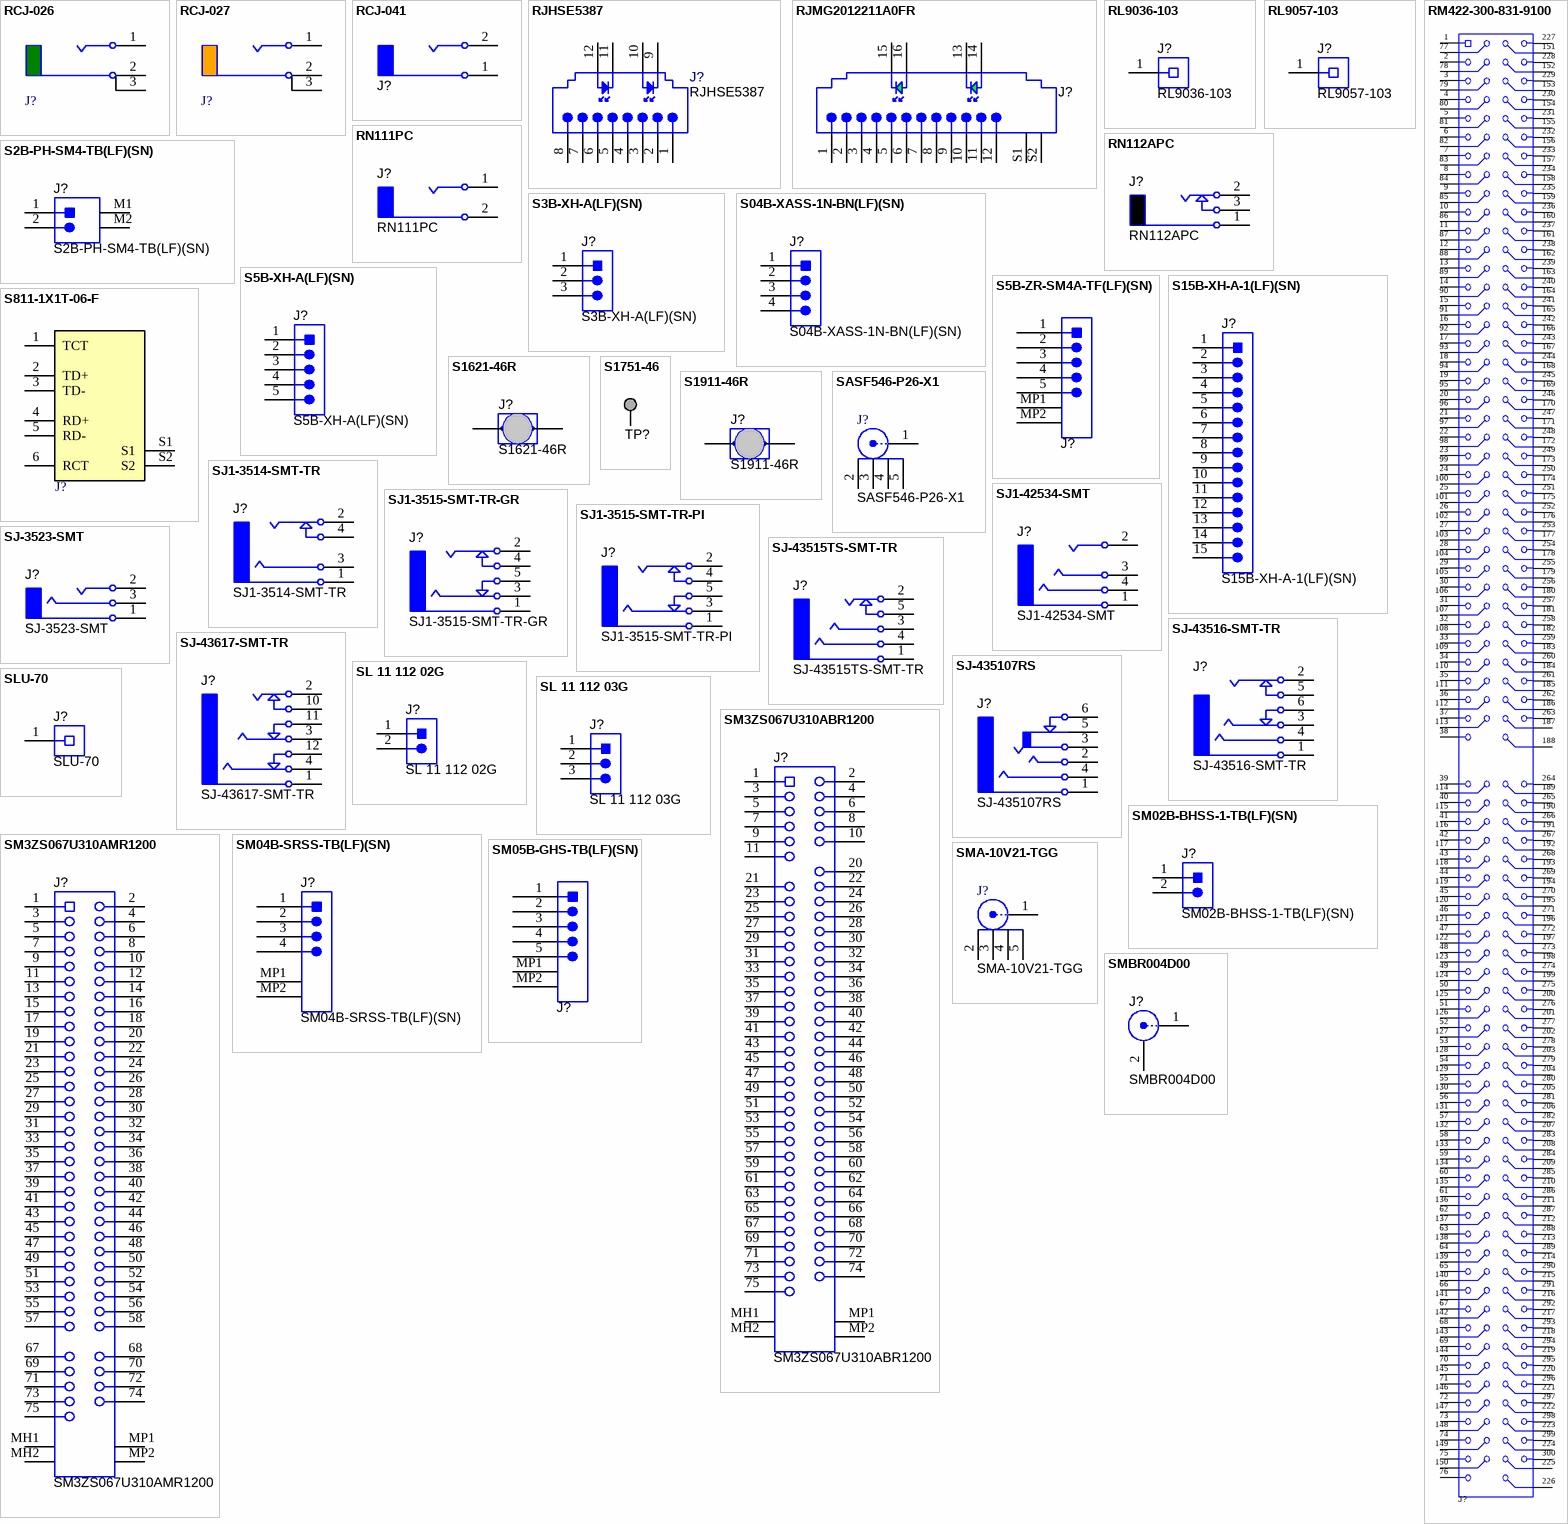
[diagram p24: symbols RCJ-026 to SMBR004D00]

## RCJ-026
designator J?  (value not drawn)
RCA Jack, Vertical, Green, TH; Manufacturer: CUI Inc.; SymbolCreator: Altium; CompType: Audio Connector; Gender: Female; ContactFinish: Tin; Voltage_V: 500
footprint CONN_RCJ-026
pins: 1 "Tip/Left Channel/(+)", 2 (power) "Sleeve (Ground)", 3 R "Ring/Right Channel/(-)"

## RCJ-027
designator J?  (value not drawn)
RCA Jack, Vertical, Orange, TH; Manufacturer: CUI Inc.; SymbolCreator: Altium; CompType: Audio Connector; Gender: Female; ContactFinish: Tin; Voltage_V: 500
footprint CONN_RCJ-027
pins: 1 "Tip/Left Channel/(+)", 2 (power) "Sleeve (Ground)", 3 R "Ring/Right Channel/(-)"

## RCJ-041
designator J?  (value not drawn)
RCA Jack, 1Pos, Tin, R/A, TH; Manufacturer: CUI Inc.; SymbolCreator: Altium; CompType: Audio Connector; Gender: Female; Row_Count: 1; Voltage_V: 500; Green_Lifecycle: Not Set; Green_REACh: Incomplete
footprint CUI_RCJ-041
pins: 1 SLEEVE "Tip/Left Channel/(+)", 2 TIP (power) "Sleeve (Ground)"

## RJHSE5387
designator J?
RJ45, Right Angle, Red/Green LED, tab up; Manufacturer: Amphenol RF; SymbolCreator: a0412235
footprint RJHSE5387
pins: 1, 2, 3, 4, 5, 6, 7, 8, 9 K1, 10 A1, 11 K2, 12 A2

## RJMG2012211A0FR
designator J?  (value not drawn)
Connector, RJ45 with integrated magnetics, R/A, TH; Manufacturer: Amphenol Canada; SymbolCreator: Altium; Pitch_mm: 2.03; Gender: Female; ContactFinish: Gold; Current_A: 0.03; Voltage_V: 5; Cert_UL: Y
footprint Amphenol_RJMG2012211A0FR
pins: 1, 2, 3, 4, 5, 6, 7, 8, 9, 10, 11, 12, 13, 14, 15, 16, S1 SHIELD1, S2 SHIELD2

## RL9036-103
designator J?
Receptacle, M4 x 0.7, 1x1, Nickel, TH; Manufacturer: Amphenol Connex; SymbolCreator: a0799628; Gender: Female; Current_A: 120
footprint Amphenol_RL9036-103
pins: 1

## RL9057-103
designator J?
Receptacle, M6 x 1.0, 1x1, Nickel, TH; Manufacturer: Amphenol Connex; SymbolCreator: a0799628; Gender: Female; Current_A: 70
footprint Amphenol_RL9057-103
pins: 1

## RM422-300-831-9100
designator J?  (value not drawn)
Receptacle, 75mil, 300 Contacts, Gold, TH; Manufacturer: Airborn; SymbolCreator: Altium; Pitch_mm: 1.905; Gender: Female; Row_Count: 4
footprint Airborn_RM422-300-83x
pins: 1, 2, 3, 4, 5, 6, 7, 8, 9, 10, 11, 12, 13, 14, 15, 16, 17, 18, 19, 20, 21, 22, 23, 24, 25, 26, 27, 28, 29, 30, 31, 32, 33, 34, 35, 36, 37, 38, 39, 40, 41, 42, 43, 44, 45, 46, 47, 48, 49, 50, 51, 52, 53, 54, 55, 56, 57, 58, 59, 60, 61, 62, 63, 64, 65, 66, 67, 68, 69, 70, 71, 72, 73, 74, 75, 76, 77, 78, 79, 80, 81, 82, 83, 84, 85, 86, 87, 88, 89, 90, 91, 92, 93, 94, 95, 96, 97, 98, 99, 100, 101, 102, 103, 104, 105, 106, 107, 108, 109, 110, 111, 112, 113, 114, 115, 116, 117, 118, 119, 120, 121, 122, 123, 124, 125, 126, 127, 128, 129, 130, 131, 132, 133, 134, 135, 136, 137, 138, 139, 140, 141, 142, 143, 144, 145, 146, 147, 148, 149, 150, 151, 152, 153, 154, 155, 156, 157, 158, 159, 160, 161, 162, 163, 164, 165, 166, 167, 168, 169, 170, 171, 172, 173, 174, 175, 176, 177, 178, 179, 180, 181, 182, 183, 184, 185, 186, 187, 188, 189, 190, 191, 192, 193, 194, 195, 196, 197, 198, 199, 200, 201, 202, 203, 204, 205, 206, 207, 208, 209, 210, 211, 212, 213, 214, 215, 216, 217, 218, 219, 220, 221, 222, 223, 224, 225, 226, 227, 228, 229, 230, 231, 232, 233, 234, 235, 236, 237, 238, 239, 240, 241, 242, 243, 244, 245, 246, 247, 248, 249, 250, 251, 252, 253, 254, 255, 256, 257, 258, 259, 260, 261, 262, 263, 264, 265, 266, 267, 268, 269, 270, 271, 272, 273, 274, 275, 276, 277, 278, 279, 280, 281, 282, 283, 284, 285, 286, 287, 288, 289, 290, 291, 292, 293, 294, 295, 296, 297, 298, 299, 300

## RN111PC
designator J?
Audio Jack, 1/4", Mono, R/A, TH; Manufacturer: Switchcraft; SymbolCreator: a0411947; CompType: Audio Connector
footprint Switchcraft_RN111PC
pins: 1 TIP, 2 SLEEVE

## RN112APC
designator J?
Audio Jack, 1/4", Headphone Phone Jack Mono, R/A, Black, TH; Manufacturer: Switchcraft; SymbolCreator: Altium; CompType: Audio Connector; Gender: Female
footprint Switchcraft_RN112APC
pins: 1 SLEEVE, 2 TIP, 3 TIP SWITCH

## S2B-PH-SM4-TB(LF)(SN)
designator J?
Header (shrouded), 2mm, 2x1, R/A, SMT; Manufacturer: JST Manufacturing; SymbolCreator: x0208326
footprint JST_S2B-PH-SM4-TB
pins: 1, 2, M1, M2

## S3B-XH-A(LF)(SN)
designator J?
Header (Shrouded), 2.5mm, 3x1, R/A, TH; Manufacturer: JST Manufacturing; SymbolCreator: a0799628; Pitch_mm: 2.5; Gender: Male; Shrouded: Y; Row_Count: 1; ContactFinish: Tin; Current_A: 3; Voltage_V: 250
footprint JST_S3B-XH-A
pins: 1, 2, 3
3 alternate drawings of the same symbol

## S04B-XASS-1N-BN(LF)(SN)
designator J?
Header(shrouded), 2.5mm, 4x1, TH; Manufacturer: JST Manufacturing; SymbolCreator: a0412235; Pitch_mm: 2.5; Gender: Male; Shrouded: Y; Row_Count: 1; ContactFinish: Tin; Current_A: 3; Voltage_V: 250
footprint JST_S04B-XASS-1N-BN
pins: 1, 2, 3, 4

## S5B-XH-A(LF)(SN)
designator J?
Header(shrouded), 2.5mm, 5x1, R/A, Tin, TH; Manufacturer: JST Manufacturing; SymbolCreator: a0412235; Pitch_mm: 2.5; Gender: Male; Shrouded: Y; Row_Count: 1; Current_A: 3; Voltage_V: 250
footprint JST_S5B-XH-A
pins: 1, 2, 3, 4, 5

## S5B-ZR-SM4A-TF(LF)(SN)
designator J?  (value not drawn)
Header(Shrouded), 1.5mm, 5x1, Tin, R/A, TH; Manufacturer: JST Manufacturing; SymbolCreator: Altium; Pitch_mm: 1.5; Gender: Male; Shrouded: Y; Row_Count: 1; Voltage_V: 50
footprint JST_S5B-ZR-SM4A-TF
pins: 1, 2, 3, 4, 5, MP1, MP2

## S15B-XH-A-1(LF)(SN)
designator J?
Header (Shrouded), 2.5 mm, 15x1, R/A, TH; Manufacturer: JST Manufacturing; SymbolCreator: Altium
footprint JST_S15B-XH-A-1
pins: 1, 2, 3, 4, 5, 6, 7, 8, 9, 10, 11, 12, 13, 14, 15

## S811-1X1T-06-F
designator J?  (value not drawn)
Connector, RJ45, 2.03mm, 6x1, Gold, R/A, SMT; Manufacturer: Bel Fuse; SymbolCreator: Altium; Pitch_mm: 2.03; Gender: Female; Shrouded: Y; Row_Count: 1
footprint Bel_S811-1X1T-06-F
pins: 1 TCT, 2 TD+, 3 TD-, 4 RD+, 5 RD-, 6 RCT, S1, S2

## S1621-46R
designator J?
JUMPER TIN SMD, SMT; Manufacturer: Harwin; SymbolCreator: a0799628; CompType: Jumper Wire; Current_A: 10; Green_Lifecycle: Active; Green_REACh: Passed
footprint Harwin_S1621-46R
pins: 1, 2

## S1751-46
designator TP?  (value not drawn)
Test Lead clips and hooks, SMT; Manufacturer: Harwin; SymbolCreator: a0412235; CompType: Test Point; ContactFinish: Tin; Current_A: 2
footprint Harwin_S1751-46
pins: 1

## S1911-46R
designator J?
JUMPER TIN SMD; Manufacturer: Harwin; SymbolCreator: a0799628; CompType: Jumper SMT; Green_Lifecycle: Active; Green_REACh: Passed
footprint HARWIN_S1911-46R
pins: 1, 2

## SASF546-P26-X1
designator J?
Connector, SMA,Vertical, Thru hole w/SMT center pin; Manufacturer: Lighthorse Technologies; SymbolCreator: X0208326; Green_Lifecycle: Not Set; Green_REACh: Incomplete
footprint CONN_LTI_SASF546-P26-X1
pins: 1, 2, 3, 4, 5

## SJ1-3514-SMT-TR
designator J?
Audio Jack, 3.5mm, Stereo, R/A, Black, SMT; Manufacturer: CUI Inc.; SymbolCreator: a0412235; CompType: Audio Connector; Green_Lifecycle: Not Set; Green_REACh: Incomplete
footprint CUI_SJ1-351x-SMT
pins: 1 SLEEVE, 2 TIP, 3 RING, 4 TIP SWITCH

## SJ1-3515-SMT-TR-GR
designator J?
Audio Jack, 3.5mm, Stereo, R/A, Green, SMT; Manufacturer: CUI Inc.; SymbolCreator: a0412235; CompType: Audio Connector
footprint CUI_SJ1-351x-SMT-GR
pins: 1 SLEEVE, 2 TIP, 3 RING, 4 TIP SWITCH, 5 RING SWITCH

## SJ1-3515-SMT-TR-PI
designator J?
Audio Jack, 3.5mm, Stereo, R/A, Pink, SMT; Manufacturer: CUI Inc.; SymbolCreator: a0412235; CompType: Audio Connector
footprint CUI_SJ1-351x-SMT-PI
pins: 1 SLEEVE, 2 TIP, 3 RING, 4 TIP SWITCH, 5 RING SWITCH

## SJ1-42534-SMT
designator J?
Audio Jack, 2.5mm, Stereo, R/A, SMT; Manufacturer: CUI Inc.; SymbolCreator: a0799628; CompType: Audio Connector
footprint CONN_CUI_SJ1-42534-SMT
pins: 1 SLEEVE, 2 TIP, 3 RING 1, 4 RING 2

## SJ-3523-SMT
designator J?
Audio Jack, 3.5mm, Stereo, R/A, SMT; Manufacturer: CUI Inc.; SymbolCreator: a0412235; CompType: Audio Connector; Green_Lifecycle: Not Set; Green_REACh: Incomplete
footprint CUI_SJ-3523-SMT
pins: 1 SLEEVE, 2 TIP, 3 RING

## SJ-43515TS-SMT-TR
designator J?
Audio Jack, 3.5mm, Stereo, R/A, SMT; Manufacturer: CUI Inc.; SymbolCreator: Altium; CompType: Audio Connector; Green_Lifecycle: Not Set; Green_REACh: Incomplete
footprint CUI_SJ-43515TS-SMT
pins: 1 SLEEVE, 2 TIP, 3 RING 1, 4 RING 2, 5 TIP SWITCH

## SJ-43516-SMT-TR
designator J?
AUDIO JACK 3.5mm 4COND, SMT; Manufacturer: CUI Inc.; SymbolCreator: Altium; CompType: Audio Connector; Gender: Female; Shrouded: N; Green_Lifecycle: Not Set; Green_REACh: Incomplete
footprint CUI_SJ-43516-SMT
pins: 1 SLEEVE, 2 TIP, 3 RING 1, 4 RING 2, 5 TIP SWITCH, 6 RING SWITCH

## SJ-43617-SMT-TR
designator J?
Audio Jack, 3.5mm, Stereo, R/A, Mid Mount SMT; Manufacturer: CUI Inc.; SymbolCreator: a0411947; CompType: Audio Connector
footprint CONN_SJ-43617-SMT
pins: 1 SLEEVE, 2 TIP, 3 RING 1, 4 RING 2, 10 TIP SWITCH, 11 RING 1 SWITCH, 12 RING 2 SWITCH

## SJ-435107RS
designator J?
Audio Jack, 3.5mm, Stereo, R/A, TH; Manufacturer: CUI Inc.; SymbolCreator: Altium; CompType: Audio Connector
footprint CUI_SJ-435107RS
pins: 1 SLEEVE, 2 TIP, 3 RING 1, 4 RING 2, 5 ISOLATED RING 1, 6 ISOLATED RING 1 SWITCH

## SL 11 112 02G
designator J?
Header, 2.54mm, 2x1, Gold, TH; Manufacturer: Fischer Elektronik; SymbolCreator: a0412235
footprint Fischer_SL-11-112-02G
pins: 1, 2
1 alternate drawing of the same symbol

## SL 11 112 03G
designator J?
Header, 2.54mm, 3x1, Gold, TH; Manufacturer: Fischer Elektronik; SymbolCreator: a0799628
footprint Fischer_SL-11-112-03G
pins: 1, 2, 3
3 alternate drawings of the same symbol

## SLU-70
designator J?
Copper Mechanical Lugs, 1x1, TH; Manufacturer: Ilsco; SymbolCreator: a0799628; CompType: Receptacle; Cert_CSA: Y
footprint Ilsco_SLU-70
pins: 1

## SM02B-BHSS-1-TB(LF)(SN)
designator J?
BHS Connector, 3.5 mm, 2x1, Tin, SMT; Manufacturer: JST Manufacturing; SymbolCreator: a0412235; CompType: Header
footprint JST_SM02B-BHSS-1-TB
pins: 1, 2
1 alternate drawing of the same symbol

## SM3ZS067U310ABR1200
designator J?
PCI Express M.2 connector, 0.5mm, B Key, Gold, R/A, SMD; Manufacturer: JAE Electronics; SymbolCreator: Altium
footprint JAE_SM3ZS067U310ABR1200
pins: 1, 2, 3, 4, 5, 6, 7, 8, 9, 10, 11, 20, 21, 22, 23, 24, 25, 26, 27, 28, 29, 30, 31, 32, 33, 34, 35, 36, 37, 38, 39, 40, 41, 42, 43, 44, 45, 46, 47, 48, 49, 50, 51, 52, 53, 54, 55, 56, 57, 58, 59, 60, 61, 62, 63, 64, 65, 66, 67, 68, 69, 70 69, 71, 72, 73, 74, 75, MH1, MH2, MP1, MP2

## SM3ZS067U310AMR1200
designator J?
PCI Express M.2 connector, 0.5mm, M Key, Gold, R/A, SMD; Manufacturer: JAE Electronics; SymbolCreator: Altium
footprint JAE_SM3ZS067U310AMR1200
pins: 1, 2, 3, 4, 5, 6, 7, 8, 9, 10, 11, 12, 13, 14, 15, 16, 17, 18, 19, 20, 21, 22, 23, 24, 25, 26, 27, 28, 29, 30, 31, 32, 33, 34, 35, 36, 37, 38, 39, 40, 41, 42, 43, 44, 45, 46, 47, 48, 49, 50, 51, 52, 53, 54, 55, 56, 57, 58, 67, 68, 69, 70, 71, 72, 73, 74, 75, MH1, MH2, MP1, MP2

## SM04B-SRSS-TB(LF)(SN)
designator J?
Header (Shrouded), 1 mm, 4x1, Tin, R/A, SMT; Manufacturer: JST Manufacturing; SymbolCreator: Altium; Pitch_mm: 1; Gender: Male; Shrouded: Y
footprint JST_SM04B-SRSS-TB
pins: 1, 2, 3, 4, MP1, MP2

## SM05B-GHS-TB(LF)(SN)
designator J?  (value not drawn)
Header(shrouded), 1.25mm, 5x1, Tin, SMT; Manufacturer: JST Manufacturing; SymbolCreator: Altium; Pitch_mm: 1.25; Gender: Male; Shrouded: Y; Row_Count: 1; Voltage_V: 50
footprint JST_SM05B-GHS-TB
pins: 1, 2, 3, 4, 5, MP1, MP2

## SMA-10V21-TGG
designator J?
Connector, SMA, Vertical, Gold, SMT; Manufacturer: Hus-Tsan Group Co., Ltd.; SymbolCreator: X0208326
footprint Hustsan_SMA-10V21-TGG
pins: 1, 2, 3, 4, 5

## SMBR004D00
designator J?
Connector, Receptacle, 50 ohm, TH; Manufacturer: JAE Electronics; SymbolCreator: Altium
footprint JAE_SMBR004D00
pins: 1, 2

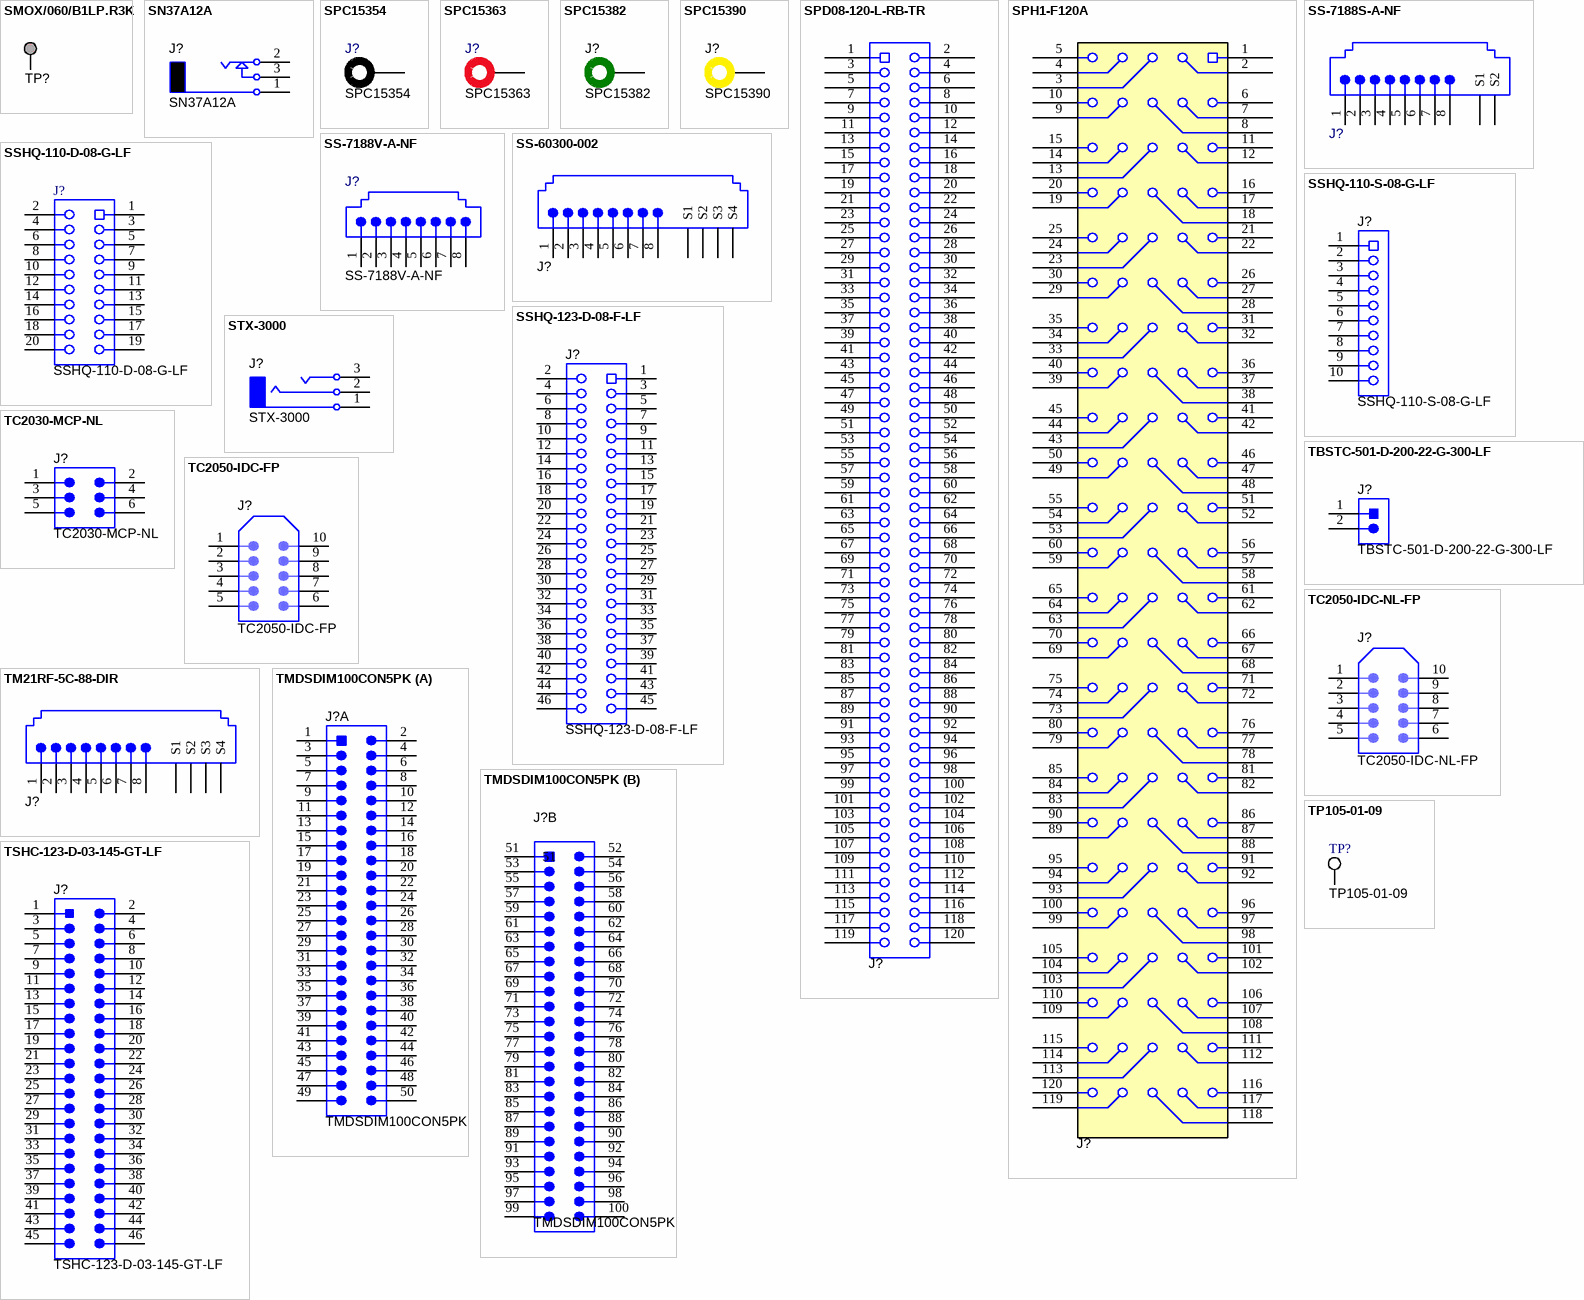
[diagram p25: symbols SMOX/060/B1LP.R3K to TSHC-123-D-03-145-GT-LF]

## SMOX/060/B1LP.R3K
designator TP?  (value not drawn)
Test Point, Silver, SMD; Manufacturer: Oxley; SymbolCreator: a0412235
footprint OXLEY_SMOX_060_B1_LP
pins: 1

## SN37A12A
designator J?
Audio Jack, 1/4", Headphone Phone Jack Mono, R/A, Nickel, Black, TH; Manufacturer: Switchcraft; SymbolCreator: Altium; CompType: Audio Connector; Gender: Female
footprint Switchcraft_SN37A12A
pins: 1 SLEEVE, 2 TIP, 3 TIP SWITCH

## SPC15354
designator J?
BANANA JACK, SOLDER LUG, BLACK, TH; Manufacturer: Tenma; SymbolCreator: a0412235; Green_Lifecycle: Not Set; Green_REACh: Incomplete
footprint Tenma_SPC15354
pins: 1

## SPC15363
designator J?
BANANA JACK, SOLDER LUG, RED, TH; Manufacturer: Tenma; SymbolCreator: a0412235; Green_Lifecycle: Not Set; Green_REACh: Incomplete
footprint Tenma_SPC15363
pins: 1

## SPC15382
designator J?
BANANA JACK, SOLDER LUG, GREEN, TH; Manufacturer: Tenma; SymbolCreator: a0411947; Gender: Female; ContactFinish: Tin
footprint Tenma_SPC15382
pins: 1

## SPC15390
designator J?
BANANA JACK, SOLDER LUG, YELLOW, TH; Manufacturer: Tenma; SymbolCreator: a0799721; Gender: Female; ContactFinish: Tin
footprint Tenma_SPC15390
pins: 1

## SPD08-120-L-RB-TR
designator J?  (value not drawn)
Receptacle, 0.8mm, 60x2, Gold, TH; Manufacturer: 3M; SymbolCreator: Altium; Pitch_mm: 0.8; Gender: Female; Shrouded: Y; Row_Count: 2; RowSpacing_mm: 3.4; Current_A: 3; Voltage_V: 50
footprint 3M_SPD08-120-L
pins: 1, 2, 3, 4, 5, 6, 7, 8, 9, 10, 11, 12, 13, 14, 15, 16, 17, 18, 19, 20, 21, 22, 23, 24, 25, 26, 27, 28, 29, 30, 31, 32, 33, 34, 35, 36, 37, 38, 39, 40, 41, 42, 43, 44, 45, 46, 47, 48, 49, 50, 51, 52, 53, 54, 55, 56, 57, 58, 59, 60, 61, 62, 63, 64, 65, 66, 67, 68, 69, 70, 71, 72, 73, 74, 75, 76, 77, 78, 79, 80, 81, 82, 83, 84, 85, 86, 87, 88, 89, 90, 91, 92, 93, 94, 95, 96, 97, 98, 99, 100, 101, 102, 103, 104, 105, 106, 107, 108, 109, 110, 111, 112, 113, 114, 115, 116, 117, 118, 119, 120

## SPH1-F120A
designator J?  (value not drawn)
Interposer, 1.27mm, 5x24; Manufacturer: Neoconix; SymbolCreator: Altium; Pitch_mm: 1.27; Row_Count: 5; ContactFinish: Gold
footprint Neoconix_SPH1-F120A
pins: 1, 2, 3, 4, 5, 6, 7, 8, 9, 10, 11, 12, 13, 14, 15, 16, 17, 18, 19, 20, 21, 22, 23, 24, 25, 26, 27, 28, 29, 30, 31, 32, 33, 34, 35, 36, 37, 38, 39, 40, 41, 42, 43, 44, 45, 46, 47, 48, 49, 50, 51, 52, 53, 54, 55, 56, 57, 58, 59, 60, 61, 62, 63, 64, 65, 66, 67, 68, 69, 70, 71, 72, 73, 74, 75, 76, 77, 78, 79, 80, 81, 82, 83, 84, 85, 86, 87, 88, 89, 90, 91, 92, 93, 94, 95, 96, 97, 98, 99, 100, 101, 102, 103, 104, 105, 106, 107, 108, 109, 110, 111, 112, 113, 114, 115, 116, 117, 118, 119, 120

## SS-7188S-A-NF
designator J?  (value not drawn)
RJ45, 1.27mm, R/A, Gold, TH; Manufacturer: Stewart Connector; SymbolCreator: Altium; Pitch_mm: 1.27; Gender: Female; Row_Count: 2; RowSpacing_mm: 2.54; Cert_UL: Y
footprint Stewart_SS-7188S-A-NF
pins: 1, 2, 3, 4, 5, 6, 7, 8, S1, S2

## SS-7188V-A-NF
designator J?
RJ45, Vertical, TH; Manufacturer: Stewart Connector; SymbolCreator: a0799628; Green_Lifecycle: Not Set; Green_REACh: Incomplete
footprint CONN_SS-7188V-A-NF
pins: 1, 2, 3, 4, 5, 6, 7, 8

## SS-60300-002
designator J?  (value not drawn)
Connector, RJ45, R/A, TH; Manufacturer: Stewart Connector; SymbolCreator: Altium; Pitch_mm: 1.02; Gender: Female; Row_Count: 2; RowSpacing_mm: 1.52; ContactFinish: Gold; Current_A: 6; Cert_UL: Y
footprint Bel_SS-60300-002
pins: 1, 2, 3, 4, 5, 6, 7, 8, S1, S2, S3, S4

## SSHQ-110-D-08-G-LF
designator J?
Receptacle, 2.54mm, 10x2, TH; Manufacturer: Major League Electronics; SymbolCreator: a0412235; Pitch_mm: 2.54; Gender: Female; Row_Count: 2; ContactFinish: Gold; Current_A: 3; Voltage_V: 600
footprint Major_SSHQ-110-D-08
pins: 1, 2, 3, 4, 5, 6, 7, 8, 9, 10, 11, 12, 13, 14, 15, 16, 17, 18, 19, 20

## SSHQ-110-S-08-G-LF
designator J?
Receptacle, 2.54mm, 10x1, TH; Manufacturer: Major League Electronics; SymbolCreator: a0411947; Pitch_mm: 2.54; Gender: Female; Row_Count: 1; ContactFinish: Gold; Current_A: 3; Voltage_V: 600
footprint Major_SSHQ-110-S-08
pins: 1, 2, 3, 4, 5, 6, 7, 8, 9, 10

## SSHQ-123-D-08-F-LF
designator J?
Female Connector, 2.54mm, 23x2, TH; Manufacturer: Major League Electronics; SymbolCreator: Altium; CompType: Receptacle
footprint Major_BBB_SSHQ-123-D-08
footprint Major_SSHQ-123-D-08
pins: 1, 2, 3, 4, 5, 6, 7, 8, 9, 10, 11, 12, 13, 14, 15, 16, 17, 18, 19, 20, 21, 22, 23, 24, 25, 26, 27, 28, 29, 30, 31, 32, 33, 34, 35, 36, 37, 38, 39, 40, 41, 42, 43, 44, 45, 46

## STX-3000
designator J?
Audio Jack, 3.5 mm, Stereo, R/A, TH; Manufacturer: Kycon Inc; SymbolCreator: Altium; CompType: Audio Connector; Green_Lifecycle: Not Set; Green_REACh: Incomplete
footprint KYCON_STX-3000
pins: 1 SLEEVE, 2 TIP, 3 RING

## TBSTC-501-D-200-22-G-300-LF
designator J?
Header, 50mil, 2x1 Double row, TH; Manufacturer: Major League Electronics; SymbolCreator: a0412235; Green_Lifecycle: Not Set; Green_REACh: Incomplete
footprint CONN_TBSTC-501-D-200-22-G-300-LF
pins: 1, 2
1 alternate drawing of the same symbol

## TC2030-MCP-NL
designator J?  (no BOM)
Footprint for TC2030-MCP-NL; Manufacturer: Tag-Connect; SymbolCreator: a0799628; CompType: Receptacle; Note: Footprint only, to mate with Tag-Connect cable P/N TC2030-MCP-NL
footprint TC2030-MCP-NL
pins: 1, 2, 3, 4, 5, 6

## TC2050-IDC-FP
designator J?  (no BOM)
Footprint for Tag-Connect TC2050 cables; SymbolCreator: Altium; CompType: Receptacle; Note: Footprint only, to mate with Tag-Connect TC2050 cables
footprint Tag_TC2050
pins: 1, 2, 3, 4, 5, 6, 7, 8, 9, 10

## TC2050-IDC-NL-FP
designator J?  (no BOM)
Footprint for Tag-Connect TC2050 No-Legs cables; SymbolCreator: Altium; CompType: Receptacle; Note: Footprint only, to mate with Tag-Connect TC2050 No-Legs cables
footprint Tag_TC2050-NL
pins: 1, 2, 3, 4, 5, 6, 7, 8, 9, 10

## TM21RF-5C-88-DIR
designator J?  (value not drawn)
Modular Connector, 1.27mm, 8 Pos, Gold, R/A, Black, TH; Manufacturer: Hirose Electric Co. Ltd.; SymbolCreator: Altium; Pitch_mm: 1.27; Gender: Female; Row_Count: 2; RowSpacing_mm: 2.54; Cert_UL: Y
footprint Hirose_TM21RF-5C-88-DIR
pins: 1, 2, 3, 4, 5, 6, 7, 8, S1, S2, S3, S4

## TMDSDIM100CON5PK
designator J?
Connector, DIM 1.27 mm 100 CKTS, An Identical Molex SD-87630-001  obsolete; Manufacturer: Texas Instruments; SymbolVersion: 20134-03-24; SymbolCreator: a0799628
footprint TI_TMDSDIM100CON5PK
part A pins: 1, 2, 3, 4, 5, 6, 7, 8, 9, 10, 11, 12, 13, 14, 15, 16, 17, 18, 19, 20, 21, 22, 23, 24, 25, 26, 27, 28, 29, 30, 31, 32, 33, 34, 35, 36, 37, 38, 39, 40, 41, 42, 43, 44, 45, 46, 47, 48, 49, 50
part B pins: 51, 52, 53, 54, 55, 56, 57, 58, 59, 60, 61, 62, 63, 64, 65, 66, 67, 68, 69, 70, 71, 72, 73, 74, 75, 76, 77, 78, 79, 80, 81, 82, 83, 84, 85, 86, 87, 88, 89, 90, 91, 92, 93, 94, 95, 96, 97, 98, 99, 100

## TP105-01-09
designator TP?
Test Point, Miniature, White, TH; Manufacturer: Components Corporation; SymbolCreator: Altium
footprint CC_TP105-01-09
pins: 1

## TSHC-123-D-03-145-GT-LF
designator J?
Header, 2.54 mm, 23x2, Gold, TH; Manufacturer: Major League Electronics; SymbolCreator: Altium; Pitch_mm: 2.54; Gender: Male; Shrouded: N; Row_Count: 2; Current_A: 3; Voltage_V: 600
footprint Major_TSHC-123-D-03-145
pins: 1, 2, 3, 4, 5, 6, 7, 8, 9, 10, 11, 12, 13, 14, 15, 16, 17, 18, 19, 20, 21, 22, 23, 24, 25, 26, 27, 28, 29, 30, 31, 32, 33, 34, 35, 36, 37, 38, 39, 40, 41, 42, 43, 44, 45, 46

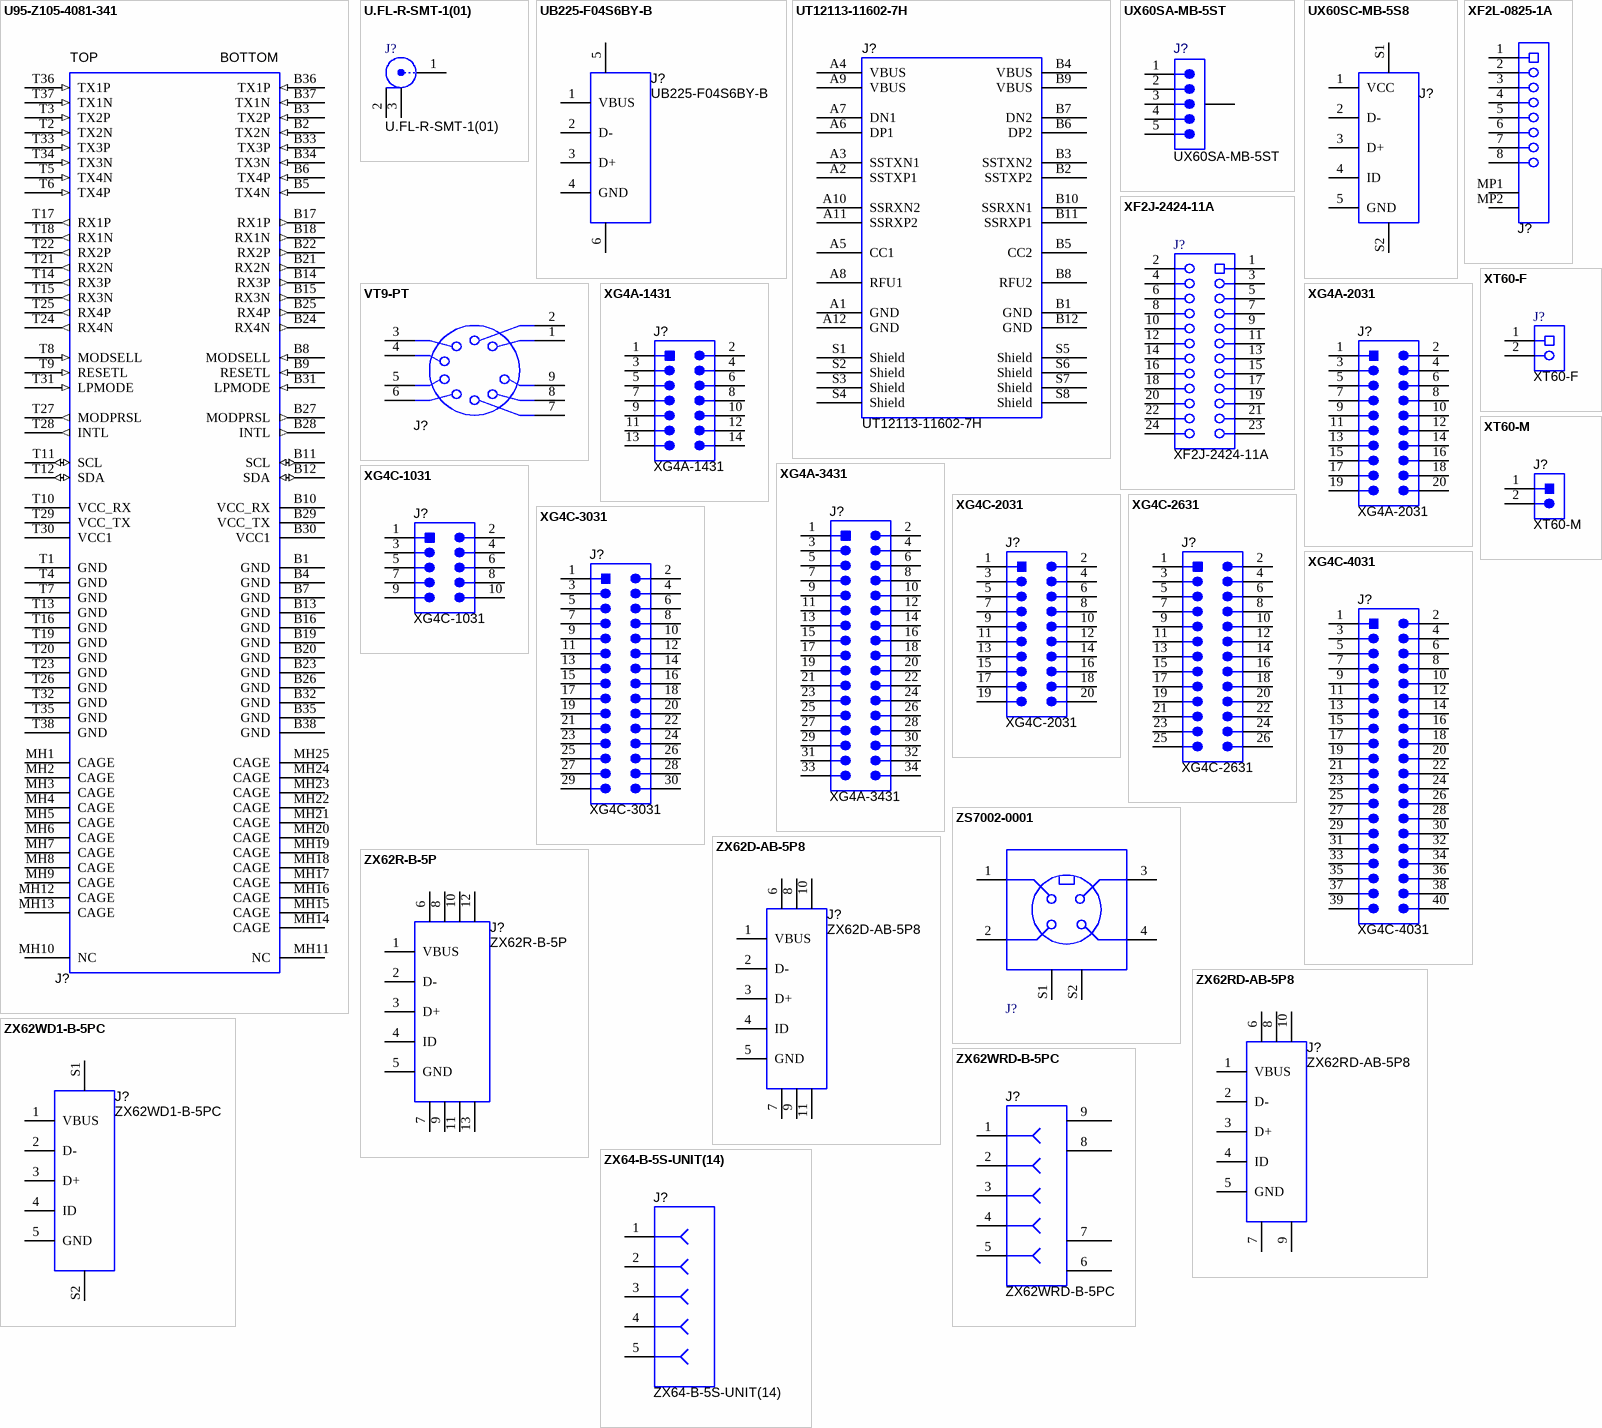
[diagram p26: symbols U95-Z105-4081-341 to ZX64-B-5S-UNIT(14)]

## U95-Z105-4081-341
designator J?  (value not drawn)
zQSFP+ Connector, 2x1 Cage EMI Fingers LP Rev, 0.8mm, 38x2, Gold, R/A, TH; Manufacturer: Amphenol-Tuchel Electronics; SymbolCreator: Altium; Pitch_mm: 0.8; Shrouded: Y; Green_Lifecycle: Not Set; Green_REACh: Incomplete
footprint Amphenol_U95-Z105-4081-341
pins: B1 GND (power), B2 TX2N (in), B3 TX2P (in), B4 GND (power), B5 TX4N (in), B6 TX4P (in), B7 GND (power), B8 MODSELL (in), B9 RESETL (in), B10 VCC_RX (power), B11 SCL (io), B12 SDA (io), B13 GND (power), B14 RX3P (out), B15 RX3N (out), B16 GND (power), B17 RX1P (out), B18 RX1N (out), B19 GND (power), B20 GND (power), B21 RX2N (out), B22 RX2P (out), B23 GND (power), B24 RX4N (out), B25 RX4P (out), B26 GND (power), B27 MODPRSL (out), B28 INTL (out), B29 VCC_TX (power), B30 VCC1 (power), B31 LPMODE (in), B32 GND (power), B33 TX3P (in), B34 TX3N (in), B35 GND (power), B36 TX1P (in), B37 TX1N (in), B38 GND (power), MH1 CAGE, MH2 CAGE, MH3 CAGE, MH4 CAGE, MH5 CAGE, MH6 CAGE, MH7 CAGE, MH8 CAGE, MH9 CAGE, MH10 NC, MH11 NC, MH12 CAGE, MH13 CAGE, MH14 CAGE, MH15 CAGE, MH16 CAGE, MH17 CAGE, MH18 CAGE, MH19 CAGE, MH20 CAGE, MH21 CAGE, MH22 CAGE, MH23 CAGE, MH24 CAGE, MH25 CAGE, T1 GND (power), T2 TX2N (in), T3 TX2P (in), T4 GND (power), T5 TX4N (in), T6 TX4P (in), T7 GND (power), T8 MODSELL (in), T9 RESETL (in), T10 VCC_RX (power), T11 SCL (io), T12 SDA (io), T13 GND (power), T14 RX3P (out), T15 RX3N (out), T16 GND (power), T17 RX1P (out), T18 RX1N (out), T19 GND (power), T20 GND (power), T21 RX2N (out), T22 RX2P (out), T23 GND (power), T24 RX4N (out), T25 RX4P (out), T26 GND (power), T27 MODPRSL (out), T28 INTL (out), T29 VCC_TX (power), T30 VCC1 (power), T31 LPMODE (in), T32 GND (power), T33 TX3P (in), T34 TX3N (in), T35 GND (power), T36 TX1P (in), T37 TX1N (in), T38 GND (power)

## U.FL-R-SMT-1(01)
designator J?
Receptacle, Ultra Miniature Coaxial, Male Pin, 50 ohm, SMT; Manufacturer: Hirose Electric Co. Ltd.; SymbolCreator: a0412235; Gender: Female; ContactFinish: Gold
footprint CONN_UFL-R-SMT-1
pins: 1, 2, 3

## UB225-F04S6BY-B
designator J?
Receptacle, USB Type A, Gold, SMT; Manufacturer: Yuqiu Electronics; SymbolCreator: a0412235; Pitch_mm: 2; Gender: Female; Row_Count: 1; Current_A: 1.5; Voltage_V: 30; Cert_UL: Y
footprint YUQIU_UB225-F04S6BY-B
pins: 1 VBUS "+5V", 2 D- "Data -", 3 D+ "Data +", 4 GND "Ground", 5 Shield, 6 Shield

## UT12113-11602-7H
designator J?
Connector, Receptacle, USB TYPE C, R/A, SMT; Manufacturer: Foxconn; SymbolCreator: Altium; Gender: Female
footprint Foxconn_UT12113-11602-7H
pins: A1 GND, A2 SSTXP1, A3 SSTXN1, A4 VBUS, A5 CC1, A6 DP1, A7 DN1, A8 RFU1, A9 VBUS, A10 SSRXN2, A11 SSRXP2, A12 GND, B1 GND, B2 SSTXP2, B3 SSTXN2, B4 VBUS, B5 CC2, B6 DP2, B7 DN2, B8 RFU2, B9 VBUS, B10 SSRXN1, B11 SSRXP1, B12 GND, S1 Shield, S2 Shield, S3 Shield, S4 Shield, S5 Shield, S6 Shield, S7 Shield, S8 Shield

## UX60SA-MB-5ST
designator J?
Connector, Receptacle, Mini-USB Type B, R/A, Top Mount SMT; Manufacturer: Hirose Electric Co. Ltd.; SymbolCreator: a0412235; CompType: USB; Gender: Female; Green_Lifecycle: Not Set; Green_REACh: Incomplete
footprint UX60SA-MB-5ST
pins: 1, 2, 3, 4, 5, 6 GND, 7 GND, 8 GND, 9 GND

## UX60SC-MB-5S8
designator J?  (value not drawn)
Connector, Receptacle, Mini-USB Type B, R/A, SMT; Manufacturer: Hirose Electric Co. Ltd.; SymbolCreator: Altium; CompType: USB; Pitch_mm: 0.8; Gender: Female; Row_Count: 1; ContactFinish: Gold; Voltage_V: 30; Cert_UL: Y
footprint Hirose_UX60SC-MB-5S8
pins: 1 VCC, 2 D-, 3 D+, 4 ID, 5 GND, S1, S2

## VT9-PT
designator J?  (value not drawn)
9 Pin Miniature Conventional Wiring and PCB Type Socket, TH; Manufacturer: Belton; SymbolCreator: Altium; Gender: Female; ContactFinish: Tin
footprint Belton_VT9-PT
pins: 1, 2, 3, 4, 5, 6, 7, 8, 9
